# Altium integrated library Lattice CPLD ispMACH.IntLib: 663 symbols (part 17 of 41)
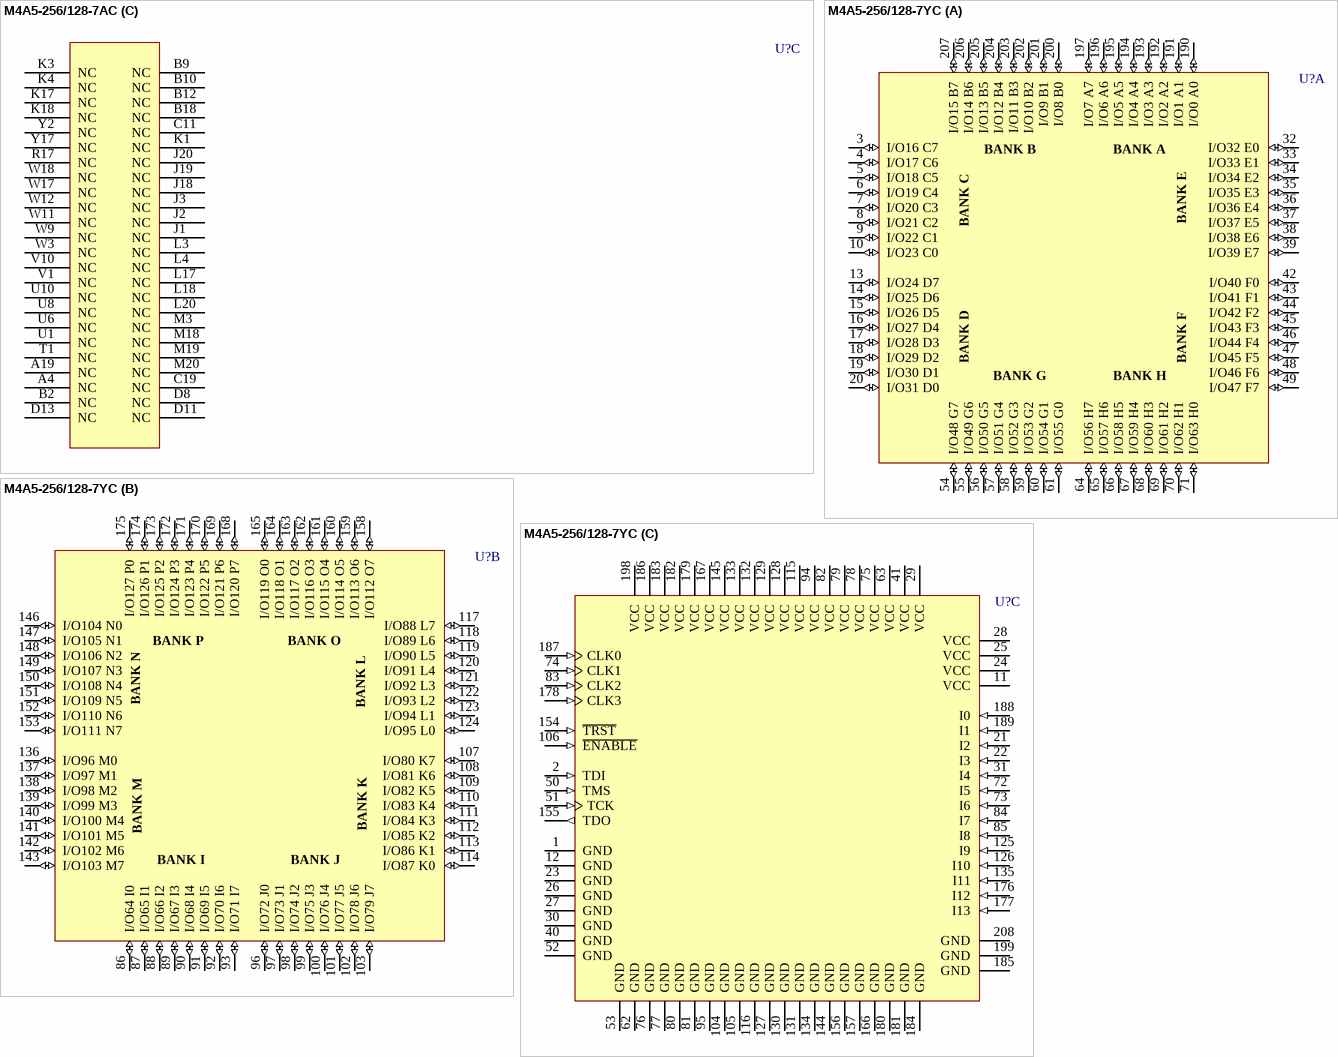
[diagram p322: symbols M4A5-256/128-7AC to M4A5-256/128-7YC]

## M4A5-256/128-7YC
designator U?
High-Performance EE CMOS In-System Programmable Logic
footprint PQFP208_N (Shrink QFP, 208-Leads, Body 28x28mm, Pitch 0.5mm, IPC Medium Density)
footprint PQFP208_L (Shrink QFP, 208-Leads, Body 28x28mm, Pitch 0.5mm, IPC High Density)
footprint PQFP208_M (Shrink QFP, 208-Leads, Body 28x28mm, Pitch 0.5mm, IPC Low Density)
3D model M4A5-PQFP208 (208-Pin Plastic Quad Flat Pack (PQFP208))
part A pins: 3 I/O16 C7 (io), 4 I/O17 C6 (io), 5 I/O18 C5 (io), 6 I/O19 C4 (io), 7 I/O20 C3 (io), 8 I/O21 C2 (io), 9 I/O22 C1 (io), 10 I/O23 C0 (io), 13 I/O24 D7 (io), 14 I/O25 D6 (io), 15 I/O26 D5 (io), 16 I/O27 D4 (io), 17 I/O28 D3 (io), 18 I/O29 D2 (io), 19 I/O30 D1 (io), 20 I/O31 D0 (io), 32 I/O32 E0 (io), 33 I/O33 E1 (io), 34 I/O34 E2 (io), 35 I/O35 E3 (io), 36 I/O36 E4 (io), 37 I/O37 E5 (io), 38 I/O38 E6 (io), 39 I/O39 E7 (io), 42 I/O40 F0 (io), 43 I/O41 F1 (io), 44 I/O42 F2 (io), 45 I/O43 F3 (io), 46 I/O44 F4 (io), 47 I/O45 F5 (io), 48 I/O46 F6 (io), 49 I/O47 F7 (io), 54 I/O48 G7 (io), 55 I/O49 G6 (io), 56 I/O50 G5 (io), 57 I/O51 G4 (io), 58 I/O52 G3 (io), 59 I/O53 G2 (io), 60 I/O54 G1 (io), 61 I/O55 G0 (io), 64 I/O56 H7 (io), 65 I/O57 H6 (io), 66 I/O58 H5 (io), 67 I/O59 H4 (io), 68 I/O60 H3 (io), 69 I/O61 H2 (io), 70 I/O62 H1 (io), 71 I/O63 H0 (io), 190 I/O0 A0 (io), 191 I/O1 A1 (io), 192 I/O2 A2 (io), 193 I/O3 A3 (io), 194 I/O4 A4 (io), 195 I/O5 A5 (io), 196 I/O6 A6 (io), 197 I/O7 A7 (io), 200 I/O8 B0 (io), 201 I/O9 B1 (io), 202 I/O10 B2 (io), 203 I/O11 B3 (io), 204 I/O12 B4 (io), 205 I/O13 B5 (io), 206 I/O14 B6 (io), 207 I/O15 B7 (io)
part B pins: 86 I/O64 I0 (io), 87 I/O65 I1 (io), 88 I/O66 I2 (io), 89 I/O67 I3 (io), 90 I/O68 I4 (io), 91 I/O69 I5 (io), 92 I/O70 I6 (io), 93 I/O71 I7 (io), 96 I/O72 J0 (io), 97 I/O73 J1 (io), 98 I/O74 J2 (io), 99 I/O75 J3 (io), 100 I/O76 J4 (io), 101 I/O77 J5 (io), 102 I/O78 J6 (io), 103 I/O79 J7 (io), 107 I/O80 K7 (io), 108 I/O81 K6 (io), 109 I/O82 K5 (io), 110 I/O83 K4 (io), 111 I/O84 K3 (io), 112 I/O85 K2 (io), 113 I/O86 K1 (io), 114 I/O87 K0 (io), 117 I/O88 L7 (io), 118 I/O89 L6 (io), 119 I/O90 L5 (io), 120 I/O91 L4 (io), 121 I/O92 L3 (io), 122 I/O93 L2 (io), 123 I/O94 L1 (io), 124 I/O95 L0 (io), 136 I/O96 M0 (io), 137 I/O97 M1 (io), 138 I/O98 M2 (io), 139 I/O99 M3 (io), 140 I/O100 M4 (io), 141 I/O101 M5 (io), 142 I/O102 M6 (io), 143 I/O103 M7 (io), 146 I/O104 N0 (io), 147 I/O105 N1 (io), 148 I/O106 N2 (io), 149 I/O107 N3 (io), 150 I/O108 N4 (io), 151 I/O109 N5 (io), 152 I/O110 N6 (io), 153 I/O111 N7 (io), 158 I/O112 O7 (io), 159 I/O113 O6 (io), 160 I/O114 O5 (io), 161 I/O115 O4 (io), 162 I/O116 O3 (io), 163 I/O117 O2 (io), 164 I/O118 O1 (io), 165 I/O119 O0 (io), 168 I/O120 P7 (io), 169 I/O121 P6 (io), 170 I/O122 P5 (io), 171 I/O123 P4 (io), 172 I/O124 P3 (io), 173 I/O125 P2 (io), 174 I/O126 P1 (io), 175 I/O127 P0 (io)
part C pins: 1 GND (power), 2 TDI (in), 11 VCC (power), 12 GND (power), 21 I2 (in), 22 I3 (in), 23 GND (power), 24 VCC (power), 25 VCC (power), 26 GND (power), 27 GND (power), 28 VCC (power), 29 VCC (power), 30 GND (power), 31 I4 (in), 40 GND (power), 41 VCC (power), 50 TMS (in), 51 TCK (in), 52 GND (power), 53 GND (power), 62 GND (power), 63 VCC (power), 72 I5 (in), 73 I6 (in), 74 CLK1 (in), 75 VCC (power), 76 GND (power), 77 GND (power), 78 VCC (power), 79 VCC (power), 80 GND (power), 81 GND (power), 82 VCC (power), 83 CLK2 (in), 84 I7 (in), 85 I8 (in), 94 VCC (power), 95 GND (power), 104 GND (power), 105 GND (power), 106 ~{ENABLE} (in), 115 VCC (power), 116 GND (power), 125 I9 (in), 126 I10 (in), 127 GND (power), 128 VCC (power), 129 VCC (power), 130 GND (power), 131 GND (power), 132 VCC (power), 133 VCC (power), 134 GND (power), 135 I11 (in), 144 GND (power), 145 VCC (power), 154 ~{TRST} (in), 155 TDO (out), 156 GND (power), 157 GND (power), 166 GND (power), 167 VCC (power), 176 I12 (in), 177 I13 (in), 178 CLK3 (in), 179 VCC (power), 180 GND (power), 181 GND (power), 182 VCC (power), 183 VCC (power), 184 GND (power), 185 GND (power), 186 VCC (power), 187 CLK0 (in), 188 I0 (in), 189 I1 (in), 198 VCC (power), 199 GND (power), 208 GND (power)

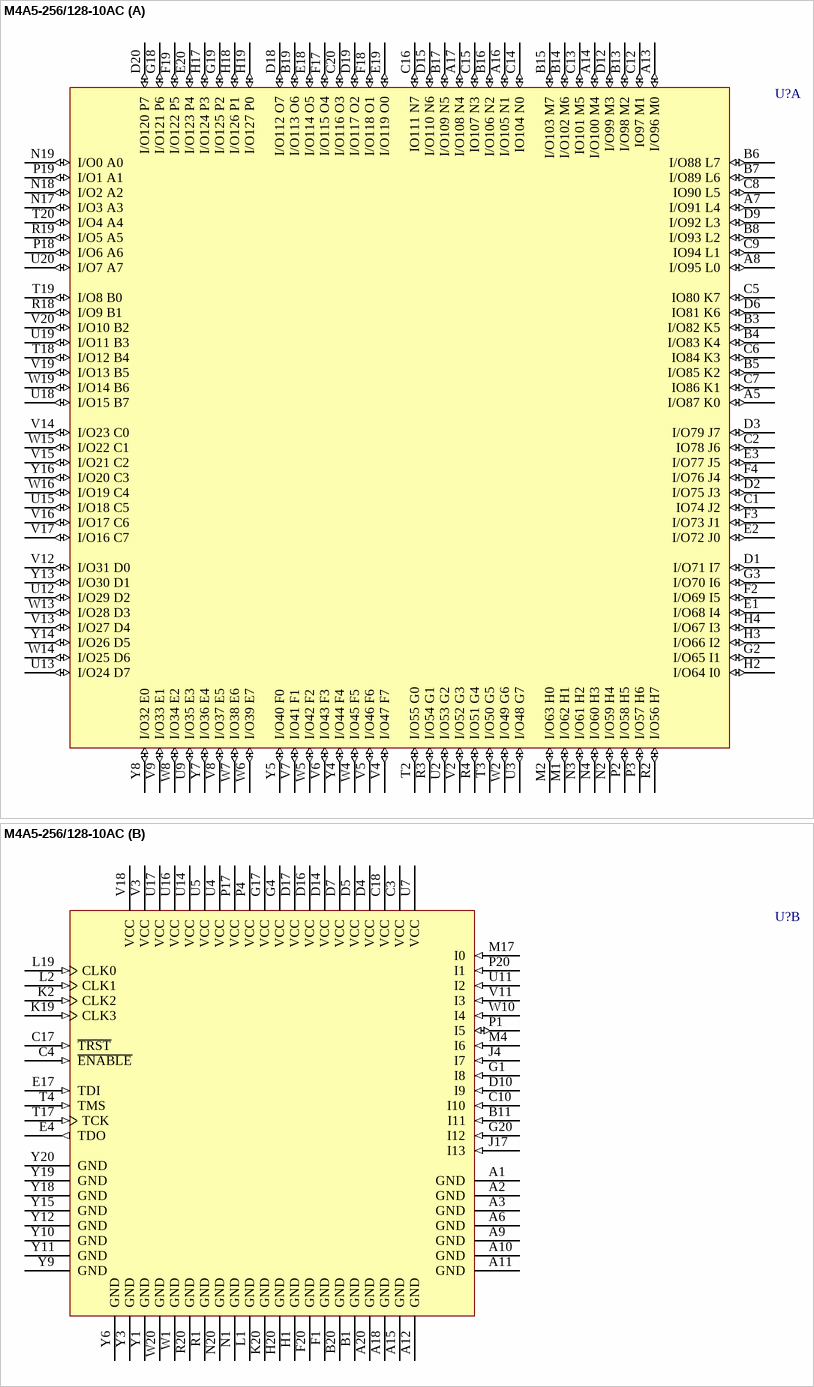
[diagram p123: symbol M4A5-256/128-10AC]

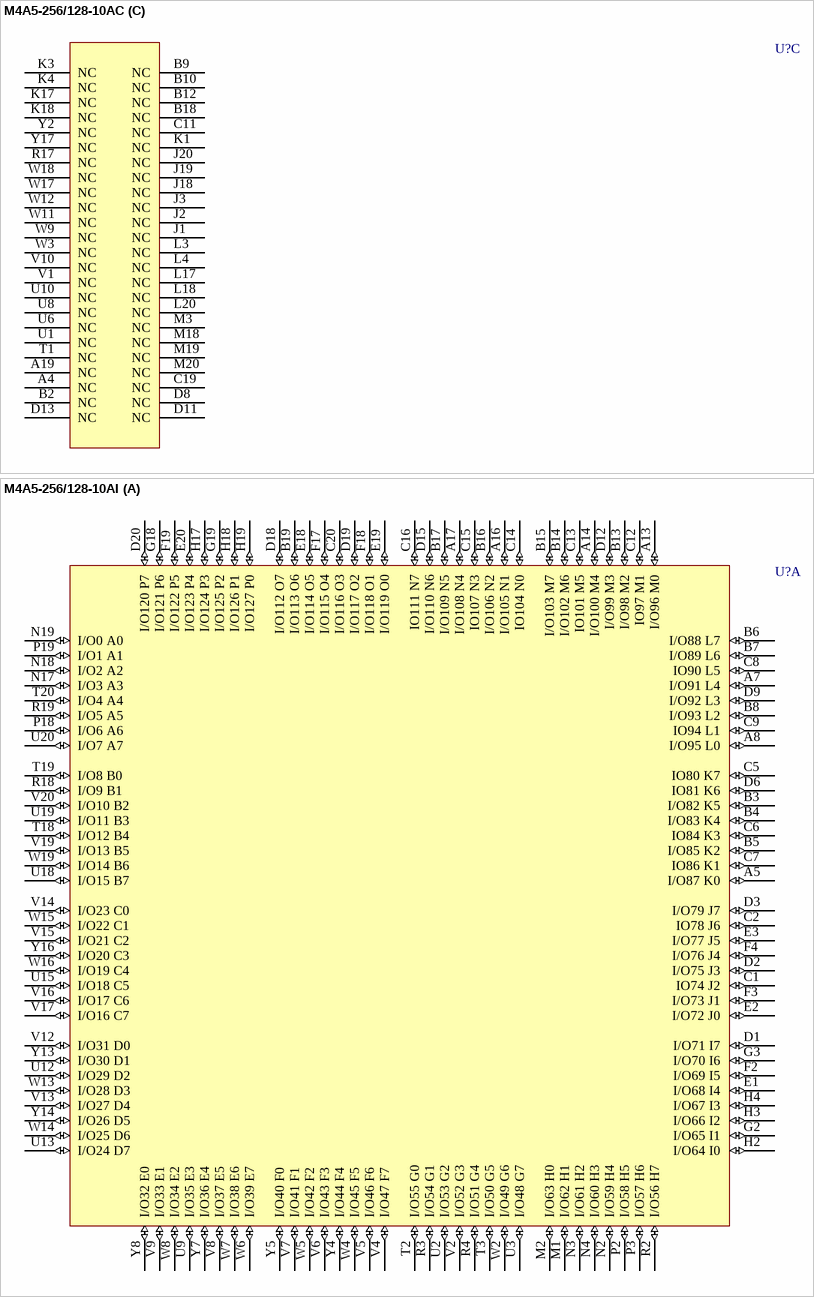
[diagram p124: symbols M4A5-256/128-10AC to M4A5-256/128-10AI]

## M4A5-256/128-10AC
designator U?
High-Performance EE CMOS In-System Programmable Logic
footprint SBGA256 (BGA, 256-Leads, Body 27x27mm, Pitch 1.27mm)
3D model M4A5-SBGA256 (256-Ball Super Ball Grid Array (SBGA256))
part A pins: A5 I/O87 K0 (io), A7 I/O91 L4 (io), A8 I/O95 L0 (io), A13 I/O96 M0 (io), A14 I/O100 M4 (io), A16 I/O105 N1 (io), A17 I/O108 N4 (io), B3 I/O82 K5 (io), B4 I/O83 K4 (io), B5 I/O85 K2 (io), B6 I/O88 L7 (io), B7 I/O89 L6 (io), B8 I/O93 L2 (io), B13 I/O98 M2 (io), B14 I/O102 M6 (io), B15 I/O103 M7 (io), B16 I/O106 N2 (io), B17 I/O109 N5 (io), B19 I/O113 O6 (io), C1 IO74 J2 (io), C2 IO78 J6 (io), C5 IO80 K7 (io), C6 IO84 K3 (io), C7 IO86 K1 (io), C8 IO90 L5 (io), C9 IO94 L1 (io), C12 IO97 M1 (io), C13 IO101 M5 (io), C14 IO104 N0 (io), C15 IO107 N3 (io), C16 IO111 N7 (io), C20 I/O116 O3 (io), D1 I/O71 I7 (io), D2 I/O75 J3 (io), D3 I/O79 J7 (io), D6 IO81 K6 (io), D9 I/O92 L3 (io), D12 I/O99 M3 (io), D15 I/O110 N6 (io), D18 I/O112 O7 (io), D19 I/O117 O2 (io), D20 I/O120 P7 (io), E1 I/O68 I4 (io), E2 I/O72 J0 (io), E3 I/O77 J5 (io), E18 I/O114 O5 (io), E19 I/O119 O0 (io), E20 I/O123 P4 (io), F2 I/O69 I5 (io), F3 I/O73 J1 (io), F4 I/O76 J4 (io), F17 I/O115 O4 (io), F18 I/O118 O1 (io), F19 I/O122 P5 (io), G2 I/O65 I1 (io), G3 I/O70 I6 (io), G18 I/O121 P6 (io), G19 I/O125 P2 (io), H2 I/O64 I0 (io), H3 I/O66 I2 (io), H4 I/O67 I3 (io), H17 I/O124 P3 (io), H18 I/O126 P1 (io), H19 I/O127 P0 (io), M1 I/O62 H1 (io), M2 I/O63 H0 (io), N2 I/O59 H4 (io), N3 I/O61 H2 (io), N4 I/O60 H3 (io), N17 I/O3 A3 (io), N18 I/O2 A2 (io), N19 I/O0 A0 (io), P2 I/O58 H5 (io), P3 I/O57 H6 (io), P18 I/O6 A6 (io), P19 I/O1 A1 (io), R2 I/O56 H7 (io), R3 I/O54 G1 (io), R4 I/O51 G4 (io), R18 I/O9 B1 (io), R19 I/O5 A5 (io), T2 I/O55 G0 (io), T3 I/O50 G5 (io), T18 I/O12 B4 (io), T19 I/O8 B0 (io), T20 I/O4 A4 (io), U2 I/O53 G2 (io), U3 I/O48 G7 (io), U9 I/O35 E3 (io), U12 I/O29 D2 (io), U13 I/O24 D7 (io), U15 I/O18 C5 (io), U18 I/O15 B7 (io), U19 I/O11 B3 (io), U20 I/O7 A7 (io), V2 I/O52 G3 (io), V4 I/O47 F7 (io), V5 I/O46 F6 (io), V6 I/O43 F3 (io), V7 I/O41 F1 (io), V8 I/O37 E5 (io), V9 I/O33 E1 (io), V12 I/O31 D0 (io), V13 I/O27 D4 (io), V14 I/O23 C0 (io), V15 I/O21 C2 (io), V16 I/O17 C6 (io), V17 I/O16 C7 (io), V19 I/O13 B5 (io), V20 I/O10 B2 (io), W2 I/O49 G6 (io), W4 I/O45 F5 (io), W5 I/O42 F2 (io), W6 I/O39 E7 (io), W7 I/O38 E6 (io), W8 I/O34 E2 (io), W13 I/O28 D3 (io), W14 I/O25 D6 (io), W15 I/O22 C1 (io), W16 I/O19 C4 (io), W19 I/O14 B6 (io), Y4 I/O44 F4 (io), Y5 I/O40 F0 (io), Y7 I/O36 E4 (io), Y8 I/O32 E0 (io), Y13 I/O30 D1 (io), Y14 I/O26 D5 (io), Y16 I/O20 C3 (io)
part B pins: A1 GND (power), A2 GND (power), A3 GND (power), A6 GND (power), A9 GND (power), A10 GND (power), A11 GND (power), A12 GND (power), A15 GND (power), A18 GND (power), A20 GND (power), B1 GND (power), B11 I11 (in), B20 GND (power), C3 VCC (power), C4 ~{ENABLE} (in), C10 I10 (in), C17 ~{TRST} (in), C18 VCC (power), D4 VCC (power), D5 VCC (power), D7 VCC (power), D10 I9 (in), D14 VCC (power), D16 VCC (power), D17 VCC (power), E4 TDO (out), E17 TDI (in), F1 GND (power), F20 GND (power), G1 I8 (in), G4 VCC (power), G17 VCC (power), G20 I12 (in), H1 GND (power), H20 GND (power), J4 I7 (in), J17 I13 (in), K2 CLK2 (in), K19 CLK3 (in), K20 GND (power), L1 GND (power), L2 CLK1 (in), L19 CLK0 (in), M4 I6 (in), M17 I0 (in), N1 GND (power), N20 GND (power), P1 I5 (io), P4 VCC (power), P17 VCC (power), P20 I1 (in), R1 GND (power), R20 GND (power), T4 TMS (in), T17 TCK (in), U4 VCC (power), U5 VCC (power), U7 VCC (power), U11 I2 (in), U14 VCC (power), U16 VCC (power), U17 VCC (power), V3 VCC (power), V11 I3 (in), V18 VCC (power), W1 GND (power), W10 I4 (in), W20 GND (power), Y1 GND (power), Y3 GND (power), Y6 GND (power), Y9 GND (power), Y10 GND (power), Y11 GND (power), Y12 GND (power), Y15 GND (power), Y18 GND (power), Y19 GND (power), Y20 GND (power)
part C pins: A4 NC, A19 NC, B2 NC, B9 NC, B10 NC, B12 NC, B18 NC, C11 NC, C19 NC, D8 NC, D11 NC, D13 NC, J1 NC, J2 NC, J3 NC, J18 NC, J19 NC, J20 NC, K1 NC, K3 NC, K4 NC, K17 NC, K18 NC, L3 NC, L4 NC, L17 NC, L18 NC, L20 NC, M3 NC, M18 NC, M19 NC, M20 NC, R17 NC, T1 NC, U1 NC, U6 NC, U8 NC, U10 NC, V1 NC, V10 NC, W3 NC, W9 NC, W11 NC, W12 NC, W17 NC, W18 NC, Y2 NC, Y17 NC

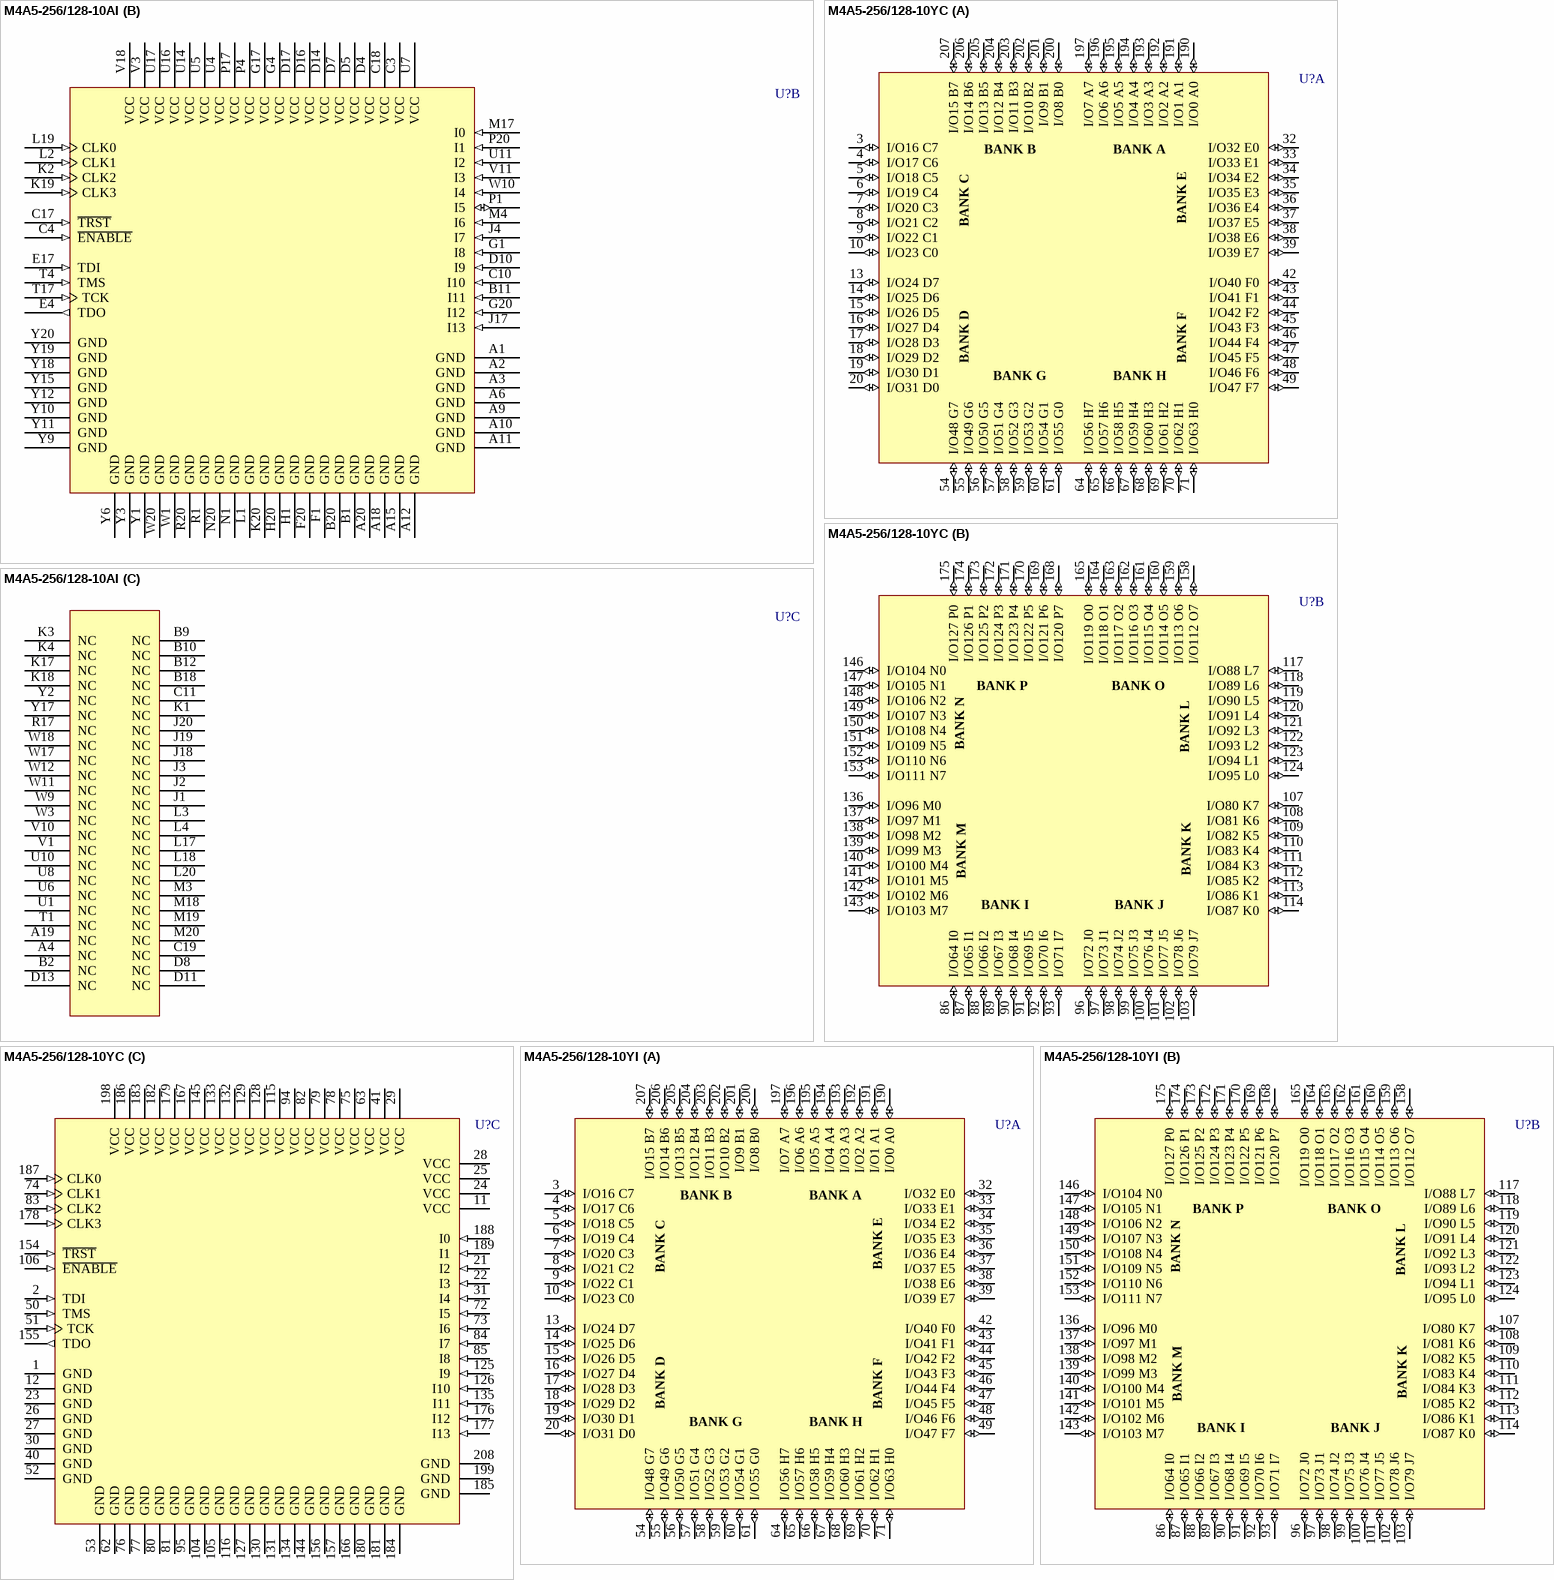
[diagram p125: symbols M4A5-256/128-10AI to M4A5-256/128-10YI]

## M4A5-256/128-10AI
designator U?
High-Performance EE CMOS In-System Programmable Logic
footprint SBGA256 (BGA, 256-Leads, Body 27x27mm, Pitch 1.27mm)
3D model M4A5-SBGA256 (256-Ball Super Ball Grid Array (SBGA256))
part A pins: A5 I/O87 K0 (io), A7 I/O91 L4 (io), A8 I/O95 L0 (io), A13 I/O96 M0 (io), A14 I/O100 M4 (io), A16 I/O105 N1 (io), A17 I/O108 N4 (io), B3 I/O82 K5 (io), B4 I/O83 K4 (io), B5 I/O85 K2 (io), B6 I/O88 L7 (io), B7 I/O89 L6 (io), B8 I/O93 L2 (io), B13 I/O98 M2 (io), B14 I/O102 M6 (io), B15 I/O103 M7 (io), B16 I/O106 N2 (io), B17 I/O109 N5 (io), B19 I/O113 O6 (io), C1 IO74 J2 (io), C2 IO78 J6 (io), C5 IO80 K7 (io), C6 IO84 K3 (io), C7 IO86 K1 (io), C8 IO90 L5 (io), C9 IO94 L1 (io), C12 IO97 M1 (io), C13 IO101 M5 (io), C14 IO104 N0 (io), C15 IO107 N3 (io), C16 IO111 N7 (io), C20 I/O116 O3 (io), D1 I/O71 I7 (io), D2 I/O75 J3 (io), D3 I/O79 J7 (io), D6 IO81 K6 (io), D9 I/O92 L3 (io), D12 I/O99 M3 (io), D15 I/O110 N6 (io), D18 I/O112 O7 (io), D19 I/O117 O2 (io), D20 I/O120 P7 (io), E1 I/O68 I4 (io), E2 I/O72 J0 (io), E3 I/O77 J5 (io), E18 I/O114 O5 (io), E19 I/O119 O0 (io), E20 I/O123 P4 (io), F2 I/O69 I5 (io), F3 I/O73 J1 (io), F4 I/O76 J4 (io), F17 I/O115 O4 (io), F18 I/O118 O1 (io), F19 I/O122 P5 (io), G2 I/O65 I1 (io), G3 I/O70 I6 (io), G18 I/O121 P6 (io), G19 I/O125 P2 (io), H2 I/O64 I0 (io), H3 I/O66 I2 (io), H4 I/O67 I3 (io), H17 I/O124 P3 (io), H18 I/O126 P1 (io), H19 I/O127 P0 (io), M1 I/O62 H1 (io), M2 I/O63 H0 (io), N2 I/O59 H4 (io), N3 I/O61 H2 (io), N4 I/O60 H3 (io), N17 I/O3 A3 (io), N18 I/O2 A2 (io), N19 I/O0 A0 (io), P2 I/O58 H5 (io), P3 I/O57 H6 (io), P18 I/O6 A6 (io), P19 I/O1 A1 (io), R2 I/O56 H7 (io), R3 I/O54 G1 (io), R4 I/O51 G4 (io), R18 I/O9 B1 (io), R19 I/O5 A5 (io), T2 I/O55 G0 (io), T3 I/O50 G5 (io), T18 I/O12 B4 (io), T19 I/O8 B0 (io), T20 I/O4 A4 (io), U2 I/O53 G2 (io), U3 I/O48 G7 (io), U9 I/O35 E3 (io), U12 I/O29 D2 (io), U13 I/O24 D7 (io), U15 I/O18 C5 (io), U18 I/O15 B7 (io), U19 I/O11 B3 (io), U20 I/O7 A7 (io), V2 I/O52 G3 (io), V4 I/O47 F7 (io), V5 I/O46 F6 (io), V6 I/O43 F3 (io), V7 I/O41 F1 (io), V8 I/O37 E5 (io), V9 I/O33 E1 (io), V12 I/O31 D0 (io), V13 I/O27 D4 (io), V14 I/O23 C0 (io), V15 I/O21 C2 (io), V16 I/O17 C6 (io), V17 I/O16 C7 (io), V19 I/O13 B5 (io), V20 I/O10 B2 (io), W2 I/O49 G6 (io), W4 I/O45 F5 (io), W5 I/O42 F2 (io), W6 I/O39 E7 (io), W7 I/O38 E6 (io), W8 I/O34 E2 (io), W13 I/O28 D3 (io), W14 I/O25 D6 (io), W15 I/O22 C1 (io), W16 I/O19 C4 (io), W19 I/O14 B6 (io), Y4 I/O44 F4 (io), Y5 I/O40 F0 (io), Y7 I/O36 E4 (io), Y8 I/O32 E0 (io), Y13 I/O30 D1 (io), Y14 I/O26 D5 (io), Y16 I/O20 C3 (io)
part B pins: A1 GND (power), A2 GND (power), A3 GND (power), A6 GND (power), A9 GND (power), A10 GND (power), A11 GND (power), A12 GND (power), A15 GND (power), A18 GND (power), A20 GND (power), B1 GND (power), B11 I11 (in), B20 GND (power), C3 VCC (power), C4 ~{ENABLE} (in), C10 I10 (in), C17 ~{TRST} (in), C18 VCC (power), D4 VCC (power), D5 VCC (power), D7 VCC (power), D10 I9 (in), D14 VCC (power), D16 VCC (power), D17 VCC (power), E4 TDO (out), E17 TDI (in), F1 GND (power), F20 GND (power), G1 I8 (in), G4 VCC (power), G17 VCC (power), G20 I12 (in), H1 GND (power), H20 GND (power), J4 I7 (in), J17 I13 (in), K2 CLK2 (in), K19 CLK3 (in), K20 GND (power), L1 GND (power), L2 CLK1 (in), L19 CLK0 (in), M4 I6 (in), M17 I0 (in), N1 GND (power), N20 GND (power), P1 I5 (io), P4 VCC (power), P17 VCC (power), P20 I1 (in), R1 GND (power), R20 GND (power), T4 TMS (in), T17 TCK (in), U4 VCC (power), U5 VCC (power), U7 VCC (power), U11 I2 (in), U14 VCC (power), U16 VCC (power), U17 VCC (power), V3 VCC (power), V11 I3 (in), V18 VCC (power), W1 GND (power), W10 I4 (in), W20 GND (power), Y1 GND (power), Y3 GND (power), Y6 GND (power), Y9 GND (power), Y10 GND (power), Y11 GND (power), Y12 GND (power), Y15 GND (power), Y18 GND (power), Y19 GND (power), Y20 GND (power)
part C pins: A4 NC, A19 NC, B2 NC, B9 NC, B10 NC, B12 NC, B18 NC, C11 NC, C19 NC, D8 NC, D11 NC, D13 NC, J1 NC, J2 NC, J3 NC, J18 NC, J19 NC, J20 NC, K1 NC, K3 NC, K4 NC, K17 NC, K18 NC, L3 NC, L4 NC, L17 NC, L18 NC, L20 NC, M3 NC, M18 NC, M19 NC, M20 NC, R17 NC, T1 NC, U1 NC, U6 NC, U8 NC, U10 NC, V1 NC, V10 NC, W3 NC, W9 NC, W11 NC, W12 NC, W17 NC, W18 NC, Y2 NC, Y17 NC

## M4A5-256/128-10YC
designator U?
High-Performance EE CMOS In-System Programmable Logic
footprint PQFP208_N (Shrink QFP, 208-Leads, Body 28x28mm, Pitch 0.5mm, IPC Medium Density)
footprint PQFP208_L (Shrink QFP, 208-Leads, Body 28x28mm, Pitch 0.5mm, IPC High Density)
footprint PQFP208_M (Shrink QFP, 208-Leads, Body 28x28mm, Pitch 0.5mm, IPC Low Density)
3D model M4A5-PQFP208 (208-Pin Plastic Quad Flat Pack (PQFP208))
part A pins: 3 I/O16 C7 (io), 4 I/O17 C6 (io), 5 I/O18 C5 (io), 6 I/O19 C4 (io), 7 I/O20 C3 (io), 8 I/O21 C2 (io), 9 I/O22 C1 (io), 10 I/O23 C0 (io), 13 I/O24 D7 (io), 14 I/O25 D6 (io), 15 I/O26 D5 (io), 16 I/O27 D4 (io), 17 I/O28 D3 (io), 18 I/O29 D2 (io), 19 I/O30 D1 (io), 20 I/O31 D0 (io), 32 I/O32 E0 (io), 33 I/O33 E1 (io), 34 I/O34 E2 (io), 35 I/O35 E3 (io), 36 I/O36 E4 (io), 37 I/O37 E5 (io), 38 I/O38 E6 (io), 39 I/O39 E7 (io), 42 I/O40 F0 (io), 43 I/O41 F1 (io), 44 I/O42 F2 (io), 45 I/O43 F3 (io), 46 I/O44 F4 (io), 47 I/O45 F5 (io), 48 I/O46 F6 (io), 49 I/O47 F7 (io), 54 I/O48 G7 (io), 55 I/O49 G6 (io), 56 I/O50 G5 (io), 57 I/O51 G4 (io), 58 I/O52 G3 (io), 59 I/O53 G2 (io), 60 I/O54 G1 (io), 61 I/O55 G0 (io), 64 I/O56 H7 (io), 65 I/O57 H6 (io), 66 I/O58 H5 (io), 67 I/O59 H4 (io), 68 I/O60 H3 (io), 69 I/O61 H2 (io), 70 I/O62 H1 (io), 71 I/O63 H0 (io), 190 I/O0 A0 (io), 191 I/O1 A1 (io), 192 I/O2 A2 (io), 193 I/O3 A3 (io), 194 I/O4 A4 (io), 195 I/O5 A5 (io), 196 I/O6 A6 (io), 197 I/O7 A7 (io), 200 I/O8 B0 (io), 201 I/O9 B1 (io), 202 I/O10 B2 (io), 203 I/O11 B3 (io), 204 I/O12 B4 (io), 205 I/O13 B5 (io), 206 I/O14 B6 (io), 207 I/O15 B7 (io)
part B pins: 86 I/O64 I0 (io), 87 I/O65 I1 (io), 88 I/O66 I2 (io), 89 I/O67 I3 (io), 90 I/O68 I4 (io), 91 I/O69 I5 (io), 92 I/O70 I6 (io), 93 I/O71 I7 (io), 96 I/O72 J0 (io), 97 I/O73 J1 (io), 98 I/O74 J2 (io), 99 I/O75 J3 (io), 100 I/O76 J4 (io), 101 I/O77 J5 (io), 102 I/O78 J6 (io), 103 I/O79 J7 (io), 107 I/O80 K7 (io), 108 I/O81 K6 (io), 109 I/O82 K5 (io), 110 I/O83 K4 (io), 111 I/O84 K3 (io), 112 I/O85 K2 (io), 113 I/O86 K1 (io), 114 I/O87 K0 (io), 117 I/O88 L7 (io), 118 I/O89 L6 (io), 119 I/O90 L5 (io), 120 I/O91 L4 (io), 121 I/O92 L3 (io), 122 I/O93 L2 (io), 123 I/O94 L1 (io), 124 I/O95 L0 (io), 136 I/O96 M0 (io), 137 I/O97 M1 (io), 138 I/O98 M2 (io), 139 I/O99 M3 (io), 140 I/O100 M4 (io), 141 I/O101 M5 (io), 142 I/O102 M6 (io), 143 I/O103 M7 (io), 146 I/O104 N0 (io), 147 I/O105 N1 (io), 148 I/O106 N2 (io), 149 I/O107 N3 (io), 150 I/O108 N4 (io), 151 I/O109 N5 (io), 152 I/O110 N6 (io), 153 I/O111 N7 (io), 158 I/O112 O7 (io), 159 I/O113 O6 (io), 160 I/O114 O5 (io), 161 I/O115 O4 (io), 162 I/O116 O3 (io), 163 I/O117 O2 (io), 164 I/O118 O1 (io), 165 I/O119 O0 (io), 168 I/O120 P7 (io), 169 I/O121 P6 (io), 170 I/O122 P5 (io), 171 I/O123 P4 (io), 172 I/O124 P3 (io), 173 I/O125 P2 (io), 174 I/O126 P1 (io), 175 I/O127 P0 (io)
part C pins: 1 GND (power), 2 TDI (in), 11 VCC (power), 12 GND (power), 21 I2 (in), 22 I3 (in), 23 GND (power), 24 VCC (power), 25 VCC (power), 26 GND (power), 27 GND (power), 28 VCC (power), 29 VCC (power), 30 GND (power), 31 I4 (in), 40 GND (power), 41 VCC (power), 50 TMS (in), 51 TCK (in), 52 GND (power), 53 GND (power), 62 GND (power), 63 VCC (power), 72 I5 (in), 73 I6 (in), 74 CLK1 (in), 75 VCC (power), 76 GND (power), 77 GND (power), 78 VCC (power), 79 VCC (power), 80 GND (power), 81 GND (power), 82 VCC (power), 83 CLK2 (in), 84 I7 (in), 85 I8 (in), 94 VCC (power), 95 GND (power), 104 GND (power), 105 GND (power), 106 ~{ENABLE} (in), 115 VCC (power), 116 GND (power), 125 I9 (in), 126 I10 (in), 127 GND (power), 128 VCC (power), 129 VCC (power), 130 GND (power), 131 GND (power), 132 VCC (power), 133 VCC (power), 134 GND (power), 135 I11 (in), 144 GND (power), 145 VCC (power), 154 ~{TRST} (in), 155 TDO (out), 156 GND (power), 157 GND (power), 166 GND (power), 167 VCC (power), 176 I12 (in), 177 I13 (in), 178 CLK3 (in), 179 VCC (power), 180 GND (power), 181 GND (power), 182 VCC (power), 183 VCC (power), 184 GND (power), 185 GND (power), 186 VCC (power), 187 CLK0 (in), 188 I0 (in), 189 I1 (in), 198 VCC (power), 199 GND (power), 208 GND (power)

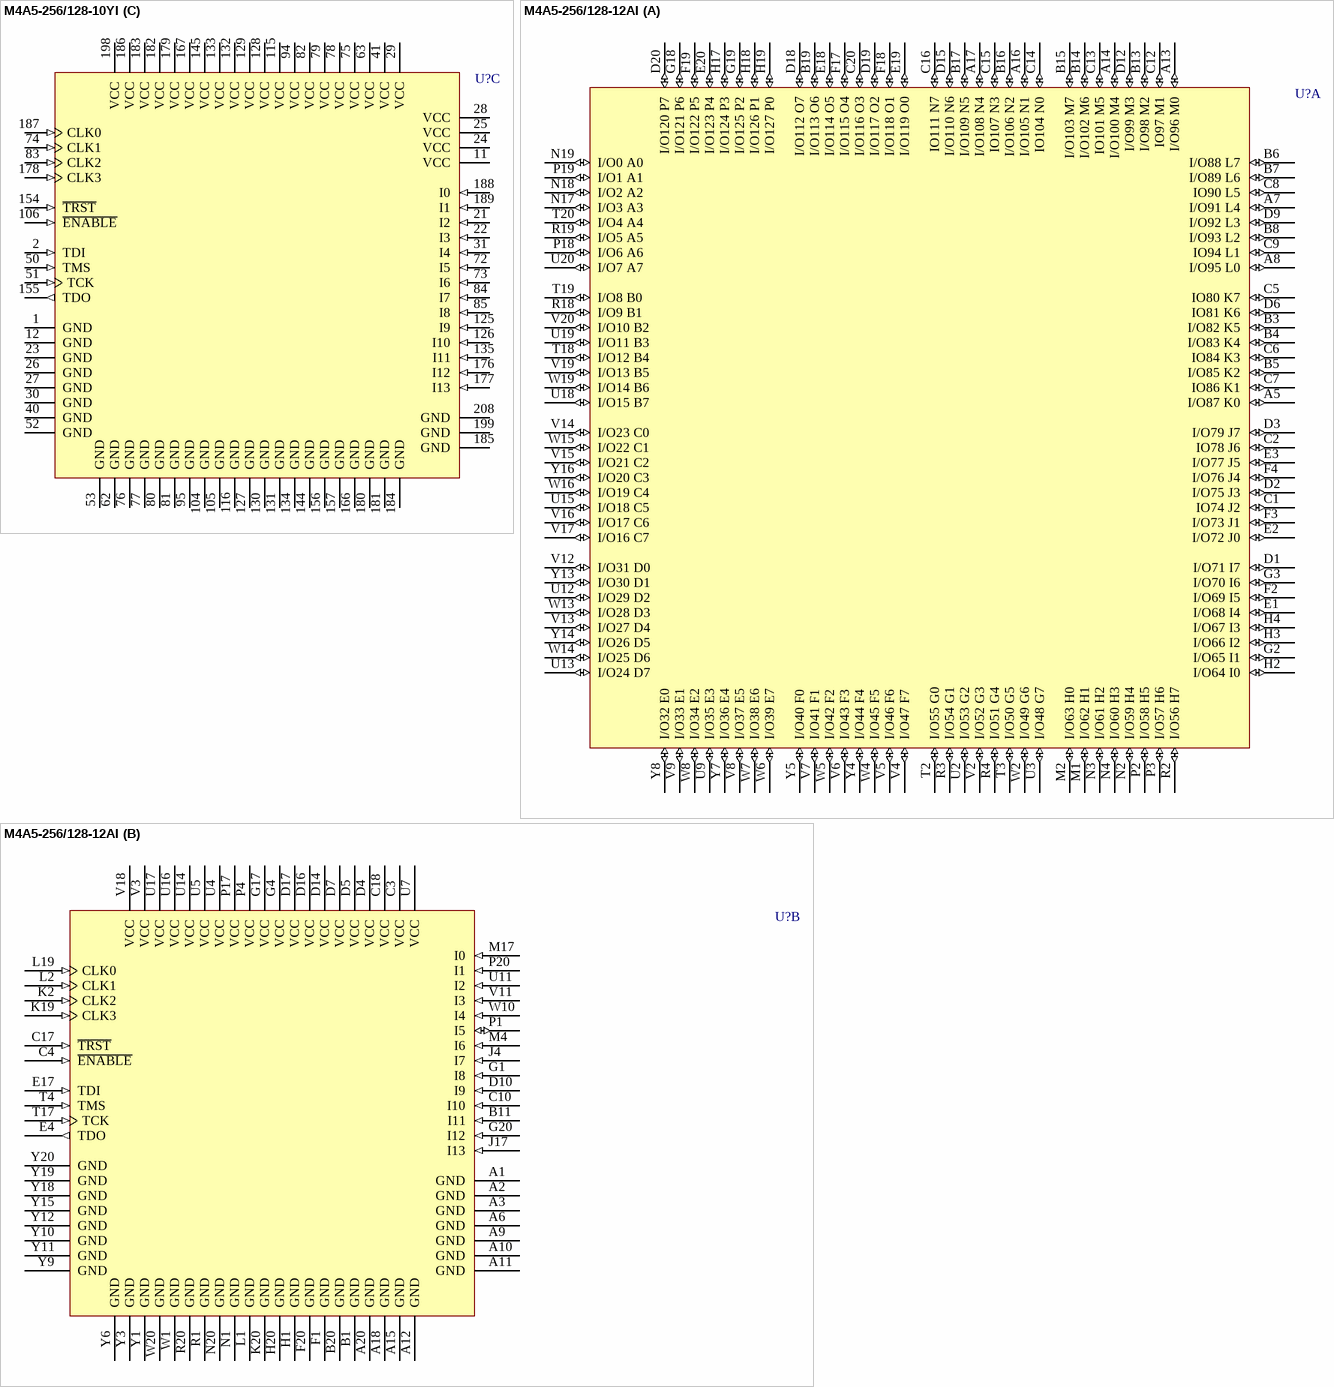
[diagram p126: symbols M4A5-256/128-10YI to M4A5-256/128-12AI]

## M4A5-256/128-10YI
designator U?
High-Performance EE CMOS In-System Programmable Logic
footprint PQFP208_N (Shrink QFP, 208-Leads, Body 28x28mm, Pitch 0.5mm, IPC Medium Density)
footprint PQFP208_L (Shrink QFP, 208-Leads, Body 28x28mm, Pitch 0.5mm, IPC High Density)
footprint PQFP208_M (Shrink QFP, 208-Leads, Body 28x28mm, Pitch 0.5mm, IPC Low Density)
3D model M4A5-PQFP208 (208-Pin Plastic Quad Flat Pack (PQFP208))
part A pins: 3 I/O16 C7 (io), 4 I/O17 C6 (io), 5 I/O18 C5 (io), 6 I/O19 C4 (io), 7 I/O20 C3 (io), 8 I/O21 C2 (io), 9 I/O22 C1 (io), 10 I/O23 C0 (io), 13 I/O24 D7 (io), 14 I/O25 D6 (io), 15 I/O26 D5 (io), 16 I/O27 D4 (io), 17 I/O28 D3 (io), 18 I/O29 D2 (io), 19 I/O30 D1 (io), 20 I/O31 D0 (io), 32 I/O32 E0 (io), 33 I/O33 E1 (io), 34 I/O34 E2 (io), 35 I/O35 E3 (io), 36 I/O36 E4 (io), 37 I/O37 E5 (io), 38 I/O38 E6 (io), 39 I/O39 E7 (io), 42 I/O40 F0 (io), 43 I/O41 F1 (io), 44 I/O42 F2 (io), 45 I/O43 F3 (io), 46 I/O44 F4 (io), 47 I/O45 F5 (io), 48 I/O46 F6 (io), 49 I/O47 F7 (io), 54 I/O48 G7 (io), 55 I/O49 G6 (io), 56 I/O50 G5 (io), 57 I/O51 G4 (io), 58 I/O52 G3 (io), 59 I/O53 G2 (io), 60 I/O54 G1 (io), 61 I/O55 G0 (io), 64 I/O56 H7 (io), 65 I/O57 H6 (io), 66 I/O58 H5 (io), 67 I/O59 H4 (io), 68 I/O60 H3 (io), 69 I/O61 H2 (io), 70 I/O62 H1 (io), 71 I/O63 H0 (io), 190 I/O0 A0 (io), 191 I/O1 A1 (io), 192 I/O2 A2 (io), 193 I/O3 A3 (io), 194 I/O4 A4 (io), 195 I/O5 A5 (io), 196 I/O6 A6 (io), 197 I/O7 A7 (io), 200 I/O8 B0 (io), 201 I/O9 B1 (io), 202 I/O10 B2 (io), 203 I/O11 B3 (io), 204 I/O12 B4 (io), 205 I/O13 B5 (io), 206 I/O14 B6 (io), 207 I/O15 B7 (io)
part B pins: 86 I/O64 I0 (io), 87 I/O65 I1 (io), 88 I/O66 I2 (io), 89 I/O67 I3 (io), 90 I/O68 I4 (io), 91 I/O69 I5 (io), 92 I/O70 I6 (io), 93 I/O71 I7 (io), 96 I/O72 J0 (io), 97 I/O73 J1 (io), 98 I/O74 J2 (io), 99 I/O75 J3 (io), 100 I/O76 J4 (io), 101 I/O77 J5 (io), 102 I/O78 J6 (io), 103 I/O79 J7 (io), 107 I/O80 K7 (io), 108 I/O81 K6 (io), 109 I/O82 K5 (io), 110 I/O83 K4 (io), 111 I/O84 K3 (io), 112 I/O85 K2 (io), 113 I/O86 K1 (io), 114 I/O87 K0 (io), 117 I/O88 L7 (io), 118 I/O89 L6 (io), 119 I/O90 L5 (io), 120 I/O91 L4 (io), 121 I/O92 L3 (io), 122 I/O93 L2 (io), 123 I/O94 L1 (io), 124 I/O95 L0 (io), 136 I/O96 M0 (io), 137 I/O97 M1 (io), 138 I/O98 M2 (io), 139 I/O99 M3 (io), 140 I/O100 M4 (io), 141 I/O101 M5 (io), 142 I/O102 M6 (io), 143 I/O103 M7 (io), 146 I/O104 N0 (io), 147 I/O105 N1 (io), 148 I/O106 N2 (io), 149 I/O107 N3 (io), 150 I/O108 N4 (io), 151 I/O109 N5 (io), 152 I/O110 N6 (io), 153 I/O111 N7 (io), 158 I/O112 O7 (io), 159 I/O113 O6 (io), 160 I/O114 O5 (io), 161 I/O115 O4 (io), 162 I/O116 O3 (io), 163 I/O117 O2 (io), 164 I/O118 O1 (io), 165 I/O119 O0 (io), 168 I/O120 P7 (io), 169 I/O121 P6 (io), 170 I/O122 P5 (io), 171 I/O123 P4 (io), 172 I/O124 P3 (io), 173 I/O125 P2 (io), 174 I/O126 P1 (io), 175 I/O127 P0 (io)
part C pins: 1 GND (power), 2 TDI (in), 11 VCC (power), 12 GND (power), 21 I2 (in), 22 I3 (in), 23 GND (power), 24 VCC (power), 25 VCC (power), 26 GND (power), 27 GND (power), 28 VCC (power), 29 VCC (power), 30 GND (power), 31 I4 (in), 40 GND (power), 41 VCC (power), 50 TMS (in), 51 TCK (in), 52 GND (power), 53 GND (power), 62 GND (power), 63 VCC (power), 72 I5 (in), 73 I6 (in), 74 CLK1 (in), 75 VCC (power), 76 GND (power), 77 GND (power), 78 VCC (power), 79 VCC (power), 80 GND (power), 81 GND (power), 82 VCC (power), 83 CLK2 (in), 84 I7 (in), 85 I8 (in), 94 VCC (power), 95 GND (power), 104 GND (power), 105 GND (power), 106 ~{ENABLE} (in), 115 VCC (power), 116 GND (power), 125 I9 (in), 126 I10 (in), 127 GND (power), 128 VCC (power), 129 VCC (power), 130 GND (power), 131 GND (power), 132 VCC (power), 133 VCC (power), 134 GND (power), 135 I11 (in), 144 GND (power), 145 VCC (power), 154 ~{TRST} (in), 155 TDO (out), 156 GND (power), 157 GND (power), 166 GND (power), 167 VCC (power), 176 I12 (in), 177 I13 (in), 178 CLK3 (in), 179 VCC (power), 180 GND (power), 181 GND (power), 182 VCC (power), 183 VCC (power), 184 GND (power), 185 GND (power), 186 VCC (power), 187 CLK0 (in), 188 I0 (in), 189 I1 (in), 198 VCC (power), 199 GND (power), 208 GND (power)

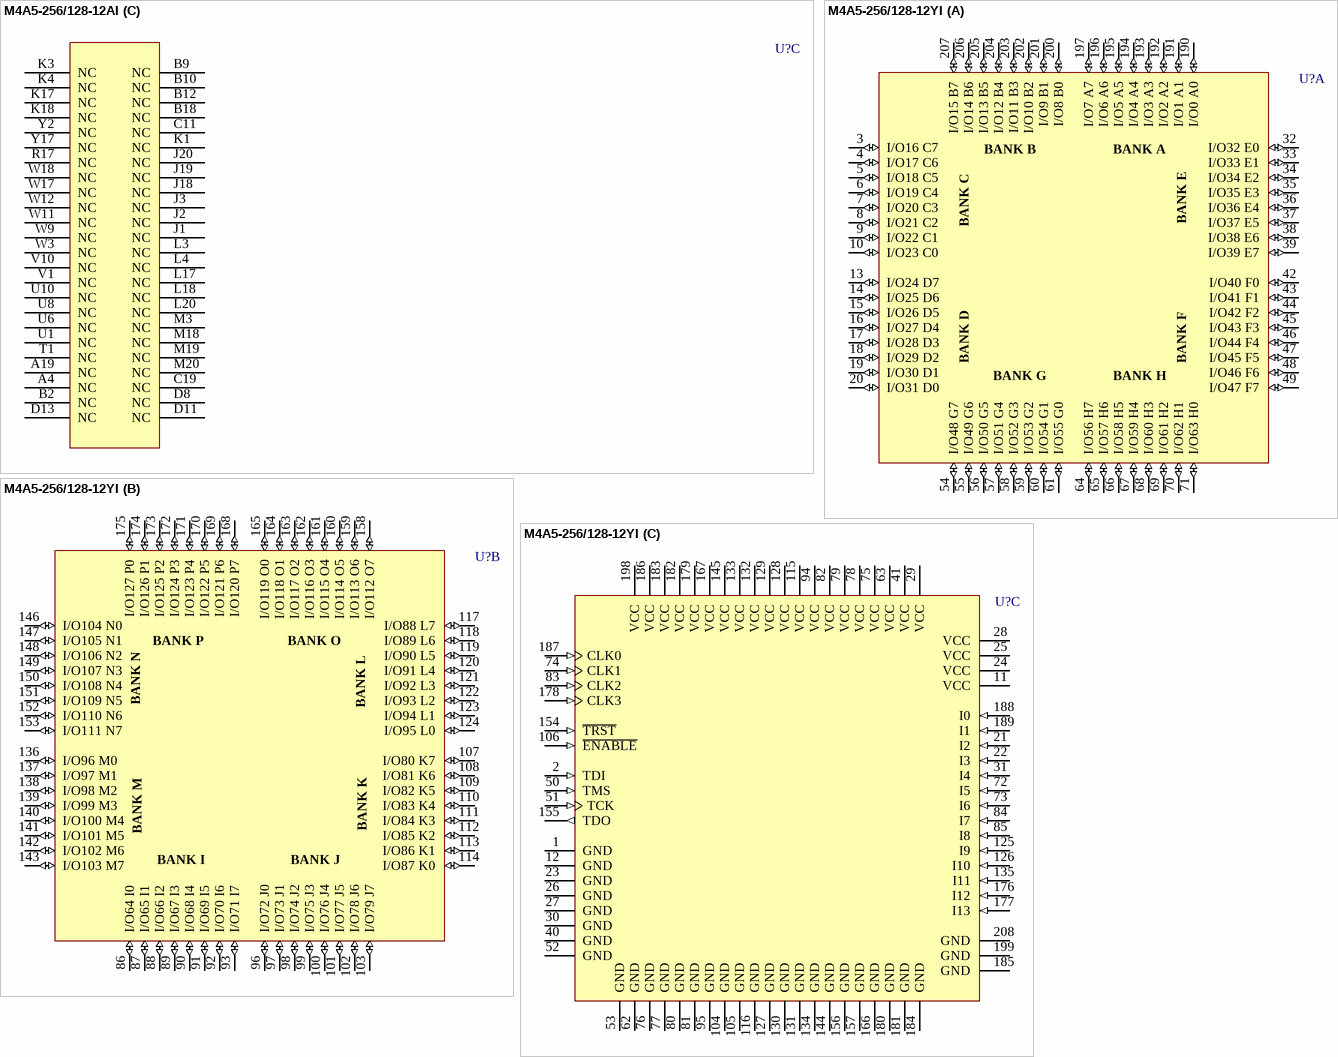
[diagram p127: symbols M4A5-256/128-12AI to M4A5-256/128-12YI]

## M4A5-256/128-12AI
designator U?
High-Performance EE CMOS In-System Programmable Logic
footprint SBGA256 (BGA, 256-Leads, Body 27x27mm, Pitch 1.27mm)
3D model M4A5-SBGA256 (256-Ball Super Ball Grid Array (SBGA256))
part A pins: A5 I/O87 K0 (io), A7 I/O91 L4 (io), A8 I/O95 L0 (io), A13 I/O96 M0 (io), A14 I/O100 M4 (io), A16 I/O105 N1 (io), A17 I/O108 N4 (io), B3 I/O82 K5 (io), B4 I/O83 K4 (io), B5 I/O85 K2 (io), B6 I/O88 L7 (io), B7 I/O89 L6 (io), B8 I/O93 L2 (io), B13 I/O98 M2 (io), B14 I/O102 M6 (io), B15 I/O103 M7 (io), B16 I/O106 N2 (io), B17 I/O109 N5 (io), B19 I/O113 O6 (io), C1 IO74 J2 (io), C2 IO78 J6 (io), C5 IO80 K7 (io), C6 IO84 K3 (io), C7 IO86 K1 (io), C8 IO90 L5 (io), C9 IO94 L1 (io), C12 IO97 M1 (io), C13 IO101 M5 (io), C14 IO104 N0 (io), C15 IO107 N3 (io), C16 IO111 N7 (io), C20 I/O116 O3 (io), D1 I/O71 I7 (io), D2 I/O75 J3 (io), D3 I/O79 J7 (io), D6 IO81 K6 (io), D9 I/O92 L3 (io), D12 I/O99 M3 (io), D15 I/O110 N6 (io), D18 I/O112 O7 (io), D19 I/O117 O2 (io), D20 I/O120 P7 (io), E1 I/O68 I4 (io), E2 I/O72 J0 (io), E3 I/O77 J5 (io), E18 I/O114 O5 (io), E19 I/O119 O0 (io), E20 I/O123 P4 (io), F2 I/O69 I5 (io), F3 I/O73 J1 (io), F4 I/O76 J4 (io), F17 I/O115 O4 (io), F18 I/O118 O1 (io), F19 I/O122 P5 (io), G2 I/O65 I1 (io), G3 I/O70 I6 (io), G18 I/O121 P6 (io), G19 I/O125 P2 (io), H2 I/O64 I0 (io), H3 I/O66 I2 (io), H4 I/O67 I3 (io), H17 I/O124 P3 (io), H18 I/O126 P1 (io), H19 I/O127 P0 (io), M1 I/O62 H1 (io), M2 I/O63 H0 (io), N2 I/O59 H4 (io), N3 I/O61 H2 (io), N4 I/O60 H3 (io), N17 I/O3 A3 (io), N18 I/O2 A2 (io), N19 I/O0 A0 (io), P2 I/O58 H5 (io), P3 I/O57 H6 (io), P18 I/O6 A6 (io), P19 I/O1 A1 (io), R2 I/O56 H7 (io), R3 I/O54 G1 (io), R4 I/O51 G4 (io), R18 I/O9 B1 (io), R19 I/O5 A5 (io), T2 I/O55 G0 (io), T3 I/O50 G5 (io), T18 I/O12 B4 (io), T19 I/O8 B0 (io), T20 I/O4 A4 (io), U2 I/O53 G2 (io), U3 I/O48 G7 (io), U9 I/O35 E3 (io), U12 I/O29 D2 (io), U13 I/O24 D7 (io), U15 I/O18 C5 (io), U18 I/O15 B7 (io), U19 I/O11 B3 (io), U20 I/O7 A7 (io), V2 I/O52 G3 (io), V4 I/O47 F7 (io), V5 I/O46 F6 (io), V6 I/O43 F3 (io), V7 I/O41 F1 (io), V8 I/O37 E5 (io), V9 I/O33 E1 (io), V12 I/O31 D0 (io), V13 I/O27 D4 (io), V14 I/O23 C0 (io), V15 I/O21 C2 (io), V16 I/O17 C6 (io), V17 I/O16 C7 (io), V19 I/O13 B5 (io), V20 I/O10 B2 (io), W2 I/O49 G6 (io), W4 I/O45 F5 (io), W5 I/O42 F2 (io), W6 I/O39 E7 (io), W7 I/O38 E6 (io), W8 I/O34 E2 (io), W13 I/O28 D3 (io), W14 I/O25 D6 (io), W15 I/O22 C1 (io), W16 I/O19 C4 (io), W19 I/O14 B6 (io), Y4 I/O44 F4 (io), Y5 I/O40 F0 (io), Y7 I/O36 E4 (io), Y8 I/O32 E0 (io), Y13 I/O30 D1 (io), Y14 I/O26 D5 (io), Y16 I/O20 C3 (io)
part B pins: A1 GND (power), A2 GND (power), A3 GND (power), A6 GND (power), A9 GND (power), A10 GND (power), A11 GND (power), A12 GND (power), A15 GND (power), A18 GND (power), A20 GND (power), B1 GND (power), B11 I11 (in), B20 GND (power), C3 VCC (power), C4 ~{ENABLE} (in), C10 I10 (in), C17 ~{TRST} (in), C18 VCC (power), D4 VCC (power), D5 VCC (power), D7 VCC (power), D10 I9 (in), D14 VCC (power), D16 VCC (power), D17 VCC (power), E4 TDO (out), E17 TDI (in), F1 GND (power), F20 GND (power), G1 I8 (in), G4 VCC (power), G17 VCC (power), G20 I12 (in), H1 GND (power), H20 GND (power), J4 I7 (in), J17 I13 (in), K2 CLK2 (in), K19 CLK3 (in), K20 GND (power), L1 GND (power), L2 CLK1 (in), L19 CLK0 (in), M4 I6 (in), M17 I0 (in), N1 GND (power), N20 GND (power), P1 I5 (io), P4 VCC (power), P17 VCC (power), P20 I1 (in), R1 GND (power), R20 GND (power), T4 TMS (in), T17 TCK (in), U4 VCC (power), U5 VCC (power), U7 VCC (power), U11 I2 (in), U14 VCC (power), U16 VCC (power), U17 VCC (power), V3 VCC (power), V11 I3 (in), V18 VCC (power), W1 GND (power), W10 I4 (in), W20 GND (power), Y1 GND (power), Y3 GND (power), Y6 GND (power), Y9 GND (power), Y10 GND (power), Y11 GND (power), Y12 GND (power), Y15 GND (power), Y18 GND (power), Y19 GND (power), Y20 GND (power)
part C pins: A4 NC, A19 NC, B2 NC, B9 NC, B10 NC, B12 NC, B18 NC, C11 NC, C19 NC, D8 NC, D11 NC, D13 NC, J1 NC, J2 NC, J3 NC, J18 NC, J19 NC, J20 NC, K1 NC, K3 NC, K4 NC, K17 NC, K18 NC, L3 NC, L4 NC, L17 NC, L18 NC, L20 NC, M3 NC, M18 NC, M19 NC, M20 NC, R17 NC, T1 NC, U1 NC, U6 NC, U8 NC, U10 NC, V1 NC, V10 NC, W3 NC, W9 NC, W11 NC, W12 NC, W17 NC, W18 NC, Y2 NC, Y17 NC

## M4A5-256/128-12YI
designator U?
High-Performance EE CMOS In-System Programmable Logic
footprint PQFP208_N (Shrink QFP, 208-Leads, Body 28x28mm, Pitch 0.5mm, IPC Medium Density)
footprint PQFP208_L (Shrink QFP, 208-Leads, Body 28x28mm, Pitch 0.5mm, IPC High Density)
footprint PQFP208_M (Shrink QFP, 208-Leads, Body 28x28mm, Pitch 0.5mm, IPC Low Density)
3D model M4A5-PQFP208 (208-Pin Plastic Quad Flat Pack (PQFP208))
part A pins: 3 I/O16 C7 (io), 4 I/O17 C6 (io), 5 I/O18 C5 (io), 6 I/O19 C4 (io), 7 I/O20 C3 (io), 8 I/O21 C2 (io), 9 I/O22 C1 (io), 10 I/O23 C0 (io), 13 I/O24 D7 (io), 14 I/O25 D6 (io), 15 I/O26 D5 (io), 16 I/O27 D4 (io), 17 I/O28 D3 (io), 18 I/O29 D2 (io), 19 I/O30 D1 (io), 20 I/O31 D0 (io), 32 I/O32 E0 (io), 33 I/O33 E1 (io), 34 I/O34 E2 (io), 35 I/O35 E3 (io), 36 I/O36 E4 (io), 37 I/O37 E5 (io), 38 I/O38 E6 (io), 39 I/O39 E7 (io), 42 I/O40 F0 (io), 43 I/O41 F1 (io), 44 I/O42 F2 (io), 45 I/O43 F3 (io), 46 I/O44 F4 (io), 47 I/O45 F5 (io), 48 I/O46 F6 (io), 49 I/O47 F7 (io), 54 I/O48 G7 (io), 55 I/O49 G6 (io), 56 I/O50 G5 (io), 57 I/O51 G4 (io), 58 I/O52 G3 (io), 59 I/O53 G2 (io), 60 I/O54 G1 (io), 61 I/O55 G0 (io), 64 I/O56 H7 (io), 65 I/O57 H6 (io), 66 I/O58 H5 (io), 67 I/O59 H4 (io), 68 I/O60 H3 (io), 69 I/O61 H2 (io), 70 I/O62 H1 (io), 71 I/O63 H0 (io), 190 I/O0 A0 (io), 191 I/O1 A1 (io), 192 I/O2 A2 (io), 193 I/O3 A3 (io), 194 I/O4 A4 (io), 195 I/O5 A5 (io), 196 I/O6 A6 (io), 197 I/O7 A7 (io), 200 I/O8 B0 (io), 201 I/O9 B1 (io), 202 I/O10 B2 (io), 203 I/O11 B3 (io), 204 I/O12 B4 (io), 205 I/O13 B5 (io), 206 I/O14 B6 (io), 207 I/O15 B7 (io)
part B pins: 86 I/O64 I0 (io), 87 I/O65 I1 (io), 88 I/O66 I2 (io), 89 I/O67 I3 (io), 90 I/O68 I4 (io), 91 I/O69 I5 (io), 92 I/O70 I6 (io), 93 I/O71 I7 (io), 96 I/O72 J0 (io), 97 I/O73 J1 (io), 98 I/O74 J2 (io), 99 I/O75 J3 (io), 100 I/O76 J4 (io), 101 I/O77 J5 (io), 102 I/O78 J6 (io), 103 I/O79 J7 (io), 107 I/O80 K7 (io), 108 I/O81 K6 (io), 109 I/O82 K5 (io), 110 I/O83 K4 (io), 111 I/O84 K3 (io), 112 I/O85 K2 (io), 113 I/O86 K1 (io), 114 I/O87 K0 (io), 117 I/O88 L7 (io), 118 I/O89 L6 (io), 119 I/O90 L5 (io), 120 I/O91 L4 (io), 121 I/O92 L3 (io), 122 I/O93 L2 (io), 123 I/O94 L1 (io), 124 I/O95 L0 (io), 136 I/O96 M0 (io), 137 I/O97 M1 (io), 138 I/O98 M2 (io), 139 I/O99 M3 (io), 140 I/O100 M4 (io), 141 I/O101 M5 (io), 142 I/O102 M6 (io), 143 I/O103 M7 (io), 146 I/O104 N0 (io), 147 I/O105 N1 (io), 148 I/O106 N2 (io), 149 I/O107 N3 (io), 150 I/O108 N4 (io), 151 I/O109 N5 (io), 152 I/O110 N6 (io), 153 I/O111 N7 (io), 158 I/O112 O7 (io), 159 I/O113 O6 (io), 160 I/O114 O5 (io), 161 I/O115 O4 (io), 162 I/O116 O3 (io), 163 I/O117 O2 (io), 164 I/O118 O1 (io), 165 I/O119 O0 (io), 168 I/O120 P7 (io), 169 I/O121 P6 (io), 170 I/O122 P5 (io), 171 I/O123 P4 (io), 172 I/O124 P3 (io), 173 I/O125 P2 (io), 174 I/O126 P1 (io), 175 I/O127 P0 (io)
part C pins: 1 GND (power), 2 TDI (in), 11 VCC (power), 12 GND (power), 21 I2 (in), 22 I3 (in), 23 GND (power), 24 VCC (power), 25 VCC (power), 26 GND (power), 27 GND (power), 28 VCC (power), 29 VCC (power), 30 GND (power), 31 I4 (in), 40 GND (power), 41 VCC (power), 50 TMS (in), 51 TCK (in), 52 GND (power), 53 GND (power), 62 GND (power), 63 VCC (power), 72 I5 (in), 73 I6 (in), 74 CLK1 (in), 75 VCC (power), 76 GND (power), 77 GND (power), 78 VCC (power), 79 VCC (power), 80 GND (power), 81 GND (power), 82 VCC (power), 83 CLK2 (in), 84 I7 (in), 85 I8 (in), 94 VCC (power), 95 GND (power), 104 GND (power), 105 GND (power), 106 ~{ENABLE} (in), 115 VCC (power), 116 GND (power), 125 I9 (in), 126 I10 (in), 127 GND (power), 128 VCC (power), 129 VCC (power), 130 GND (power), 131 GND (power), 132 VCC (power), 133 VCC (power), 134 GND (power), 135 I11 (in), 144 GND (power), 145 VCC (power), 154 ~{TRST} (in), 155 TDO (out), 156 GND (power), 157 GND (power), 166 GND (power), 167 VCC (power), 176 I12 (in), 177 I13 (in), 178 CLK3 (in), 179 VCC (power), 180 GND (power), 181 GND (power), 182 VCC (power), 183 VCC (power), 184 GND (power), 185 GND (power), 186 VCC (power), 187 CLK0 (in), 188 I0 (in), 189 I1 (in), 198 VCC (power), 199 GND (power), 208 GND (power)

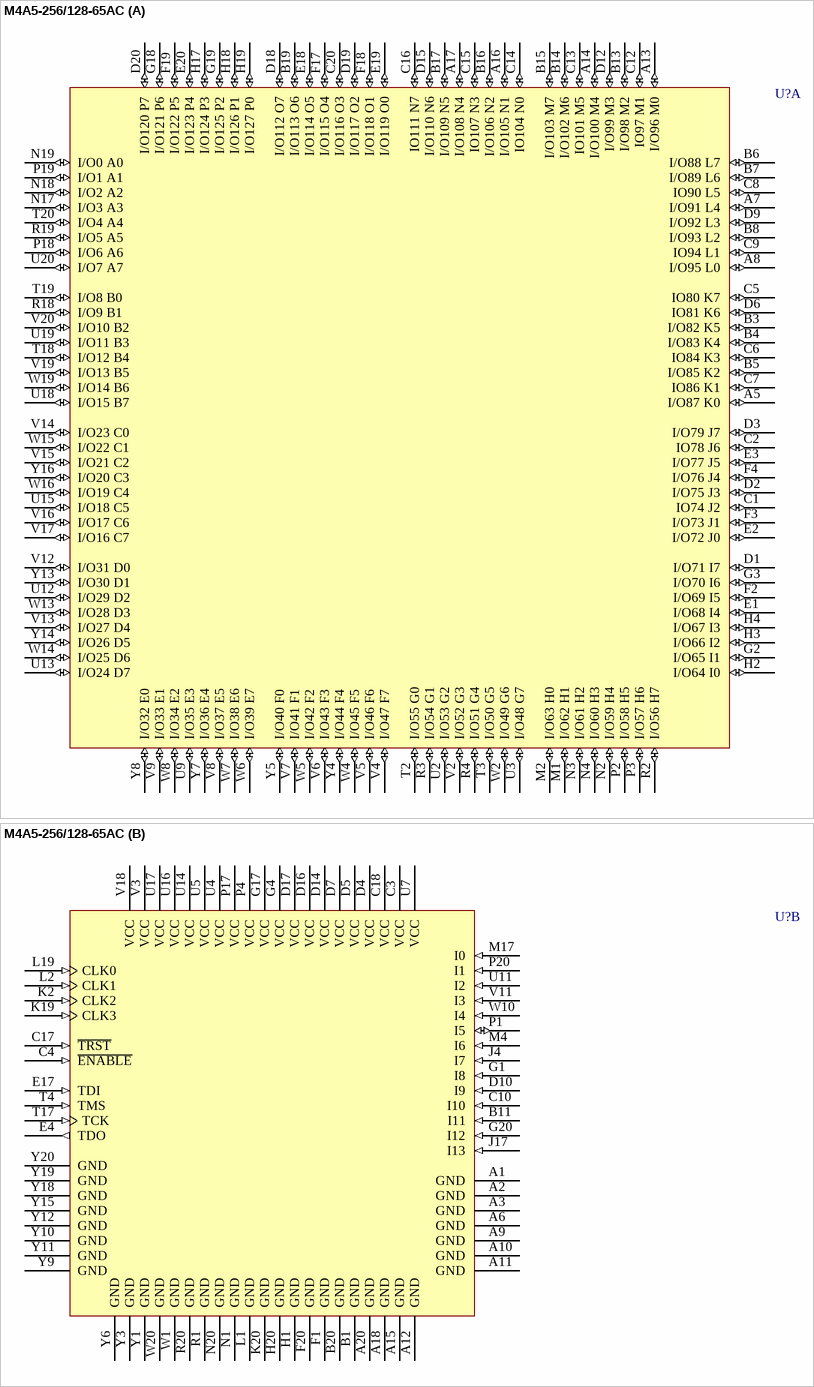
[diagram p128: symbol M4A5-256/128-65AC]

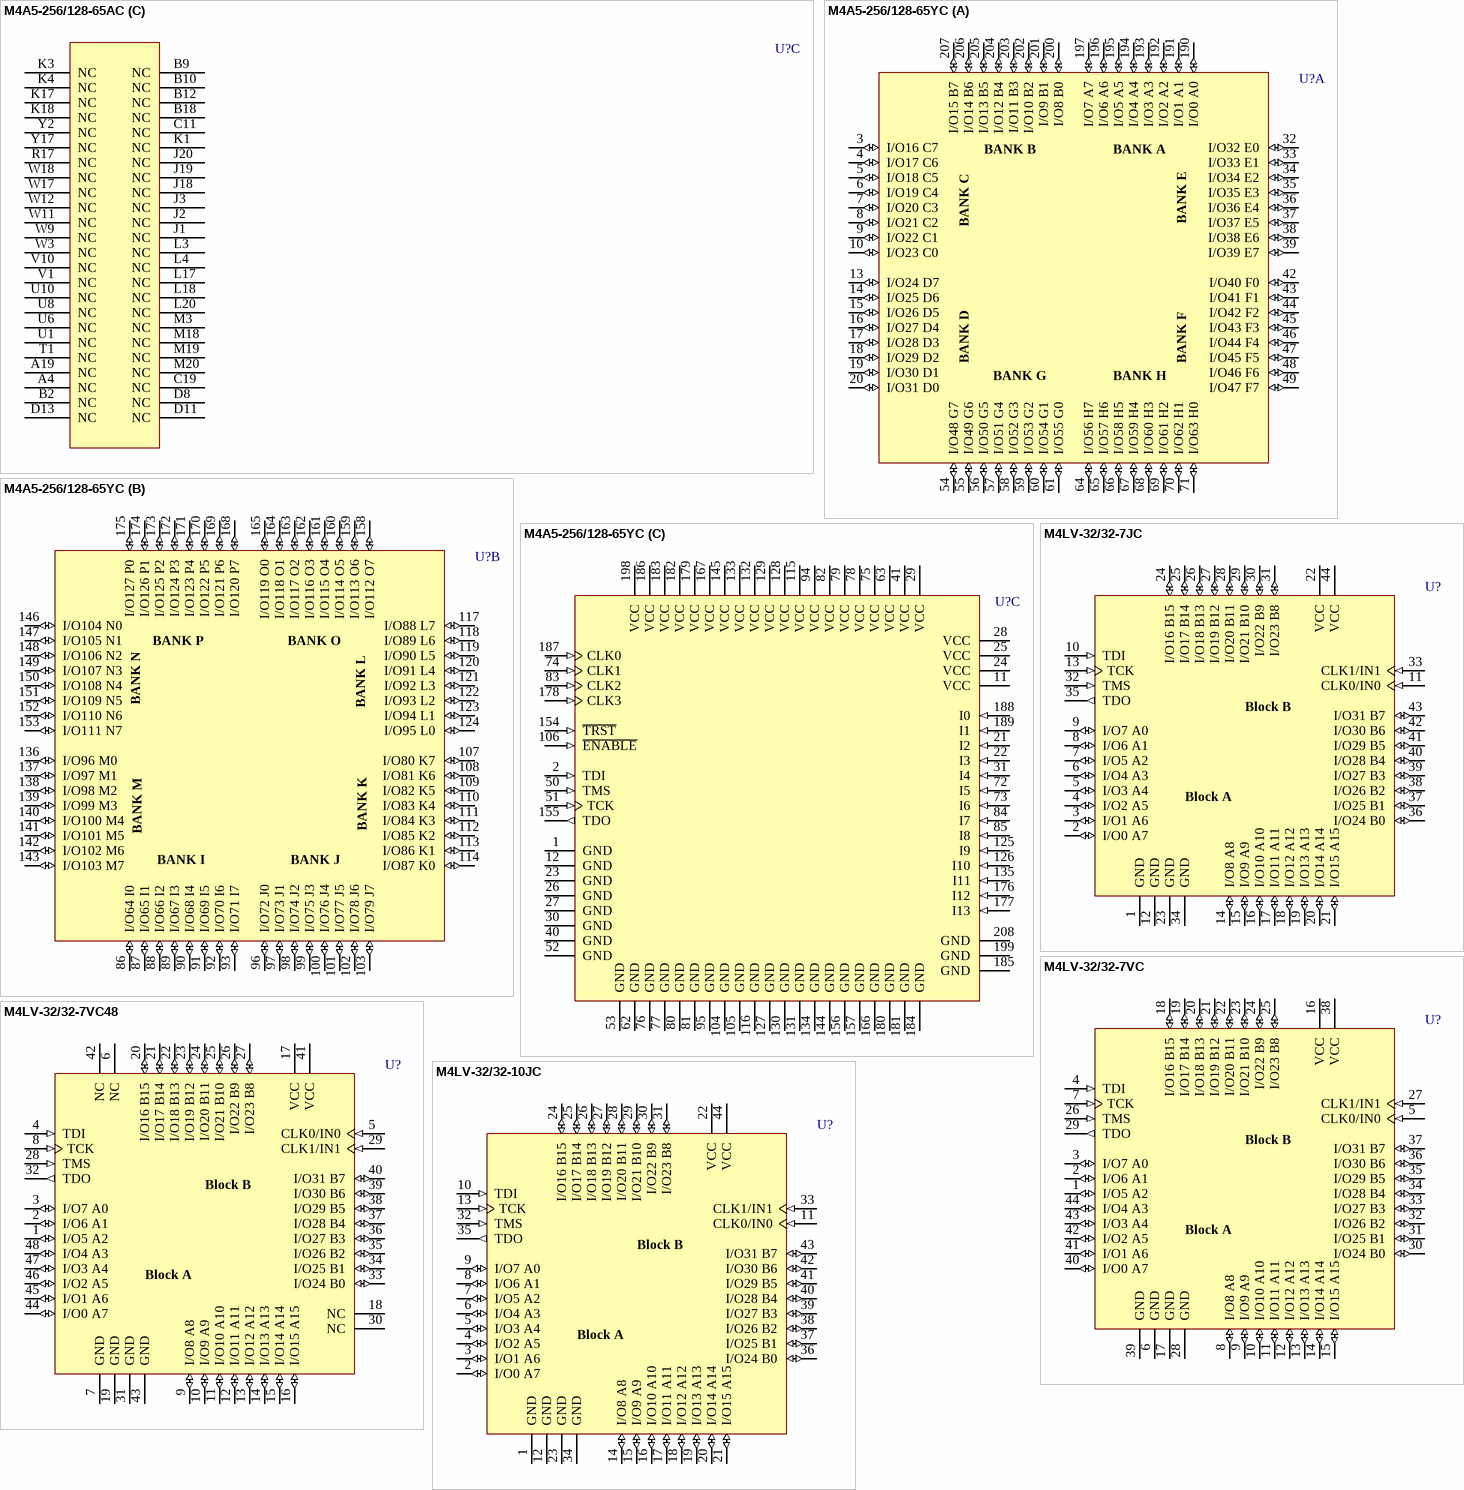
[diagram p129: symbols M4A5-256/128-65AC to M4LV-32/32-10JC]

## M4A5-256/128-65AC
designator U?
High-Performance EE CMOS In-System Programmable Logic
footprint SBGA256 (BGA, 256-Leads, Body 27x27mm, Pitch 1.27mm)
3D model M4A5-SBGA256 (256-Ball Super Ball Grid Array (SBGA256))
part A pins: A5 I/O87 K0 (io), A7 I/O91 L4 (io), A8 I/O95 L0 (io), A13 I/O96 M0 (io), A14 I/O100 M4 (io), A16 I/O105 N1 (io), A17 I/O108 N4 (io), B3 I/O82 K5 (io), B4 I/O83 K4 (io), B5 I/O85 K2 (io), B6 I/O88 L7 (io), B7 I/O89 L6 (io), B8 I/O93 L2 (io), B13 I/O98 M2 (io), B14 I/O102 M6 (io), B15 I/O103 M7 (io), B16 I/O106 N2 (io), B17 I/O109 N5 (io), B19 I/O113 O6 (io), C1 IO74 J2 (io), C2 IO78 J6 (io), C5 IO80 K7 (io), C6 IO84 K3 (io), C7 IO86 K1 (io), C8 IO90 L5 (io), C9 IO94 L1 (io), C12 IO97 M1 (io), C13 IO101 M5 (io), C14 IO104 N0 (io), C15 IO107 N3 (io), C16 IO111 N7 (io), C20 I/O116 O3 (io), D1 I/O71 I7 (io), D2 I/O75 J3 (io), D3 I/O79 J7 (io), D6 IO81 K6 (io), D9 I/O92 L3 (io), D12 I/O99 M3 (io), D15 I/O110 N6 (io), D18 I/O112 O7 (io), D19 I/O117 O2 (io), D20 I/O120 P7 (io), E1 I/O68 I4 (io), E2 I/O72 J0 (io), E3 I/O77 J5 (io), E18 I/O114 O5 (io), E19 I/O119 O0 (io), E20 I/O123 P4 (io), F2 I/O69 I5 (io), F3 I/O73 J1 (io), F4 I/O76 J4 (io), F17 I/O115 O4 (io), F18 I/O118 O1 (io), F19 I/O122 P5 (io), G2 I/O65 I1 (io), G3 I/O70 I6 (io), G18 I/O121 P6 (io), G19 I/O125 P2 (io), H2 I/O64 I0 (io), H3 I/O66 I2 (io), H4 I/O67 I3 (io), H17 I/O124 P3 (io), H18 I/O126 P1 (io), H19 I/O127 P0 (io), M1 I/O62 H1 (io), M2 I/O63 H0 (io), N2 I/O59 H4 (io), N3 I/O61 H2 (io), N4 I/O60 H3 (io), N17 I/O3 A3 (io), N18 I/O2 A2 (io), N19 I/O0 A0 (io), P2 I/O58 H5 (io), P3 I/O57 H6 (io), P18 I/O6 A6 (io), P19 I/O1 A1 (io), R2 I/O56 H7 (io), R3 I/O54 G1 (io), R4 I/O51 G4 (io), R18 I/O9 B1 (io), R19 I/O5 A5 (io), T2 I/O55 G0 (io), T3 I/O50 G5 (io), T18 I/O12 B4 (io), T19 I/O8 B0 (io), T20 I/O4 A4 (io), U2 I/O53 G2 (io), U3 I/O48 G7 (io), U9 I/O35 E3 (io), U12 I/O29 D2 (io), U13 I/O24 D7 (io), U15 I/O18 C5 (io), U18 I/O15 B7 (io), U19 I/O11 B3 (io), U20 I/O7 A7 (io), V2 I/O52 G3 (io), V4 I/O47 F7 (io), V5 I/O46 F6 (io), V6 I/O43 F3 (io), V7 I/O41 F1 (io), V8 I/O37 E5 (io), V9 I/O33 E1 (io), V12 I/O31 D0 (io), V13 I/O27 D4 (io), V14 I/O23 C0 (io), V15 I/O21 C2 (io), V16 I/O17 C6 (io), V17 I/O16 C7 (io), V19 I/O13 B5 (io), V20 I/O10 B2 (io), W2 I/O49 G6 (io), W4 I/O45 F5 (io), W5 I/O42 F2 (io), W6 I/O39 E7 (io), W7 I/O38 E6 (io), W8 I/O34 E2 (io), W13 I/O28 D3 (io), W14 I/O25 D6 (io), W15 I/O22 C1 (io), W16 I/O19 C4 (io), W19 I/O14 B6 (io), Y4 I/O44 F4 (io), Y5 I/O40 F0 (io), Y7 I/O36 E4 (io), Y8 I/O32 E0 (io), Y13 I/O30 D1 (io), Y14 I/O26 D5 (io), Y16 I/O20 C3 (io)
part B pins: A1 GND (power), A2 GND (power), A3 GND (power), A6 GND (power), A9 GND (power), A10 GND (power), A11 GND (power), A12 GND (power), A15 GND (power), A18 GND (power), A20 GND (power), B1 GND (power), B11 I11 (in), B20 GND (power), C3 VCC (power), C4 ~{ENABLE} (in), C10 I10 (in), C17 ~{TRST} (in), C18 VCC (power), D4 VCC (power), D5 VCC (power), D7 VCC (power), D10 I9 (in), D14 VCC (power), D16 VCC (power), D17 VCC (power), E4 TDO (out), E17 TDI (in), F1 GND (power), F20 GND (power), G1 I8 (in), G4 VCC (power), G17 VCC (power), G20 I12 (in), H1 GND (power), H20 GND (power), J4 I7 (in), J17 I13 (in), K2 CLK2 (in), K19 CLK3 (in), K20 GND (power), L1 GND (power), L2 CLK1 (in), L19 CLK0 (in), M4 I6 (in), M17 I0 (in), N1 GND (power), N20 GND (power), P1 I5 (io), P4 VCC (power), P17 VCC (power), P20 I1 (in), R1 GND (power), R20 GND (power), T4 TMS (in), T17 TCK (in), U4 VCC (power), U5 VCC (power), U7 VCC (power), U11 I2 (in), U14 VCC (power), U16 VCC (power), U17 VCC (power), V3 VCC (power), V11 I3 (in), V18 VCC (power), W1 GND (power), W10 I4 (in), W20 GND (power), Y1 GND (power), Y3 GND (power), Y6 GND (power), Y9 GND (power), Y10 GND (power), Y11 GND (power), Y12 GND (power), Y15 GND (power), Y18 GND (power), Y19 GND (power), Y20 GND (power)
part C pins: A4 NC, A19 NC, B2 NC, B9 NC, B10 NC, B12 NC, B18 NC, C11 NC, C19 NC, D8 NC, D11 NC, D13 NC, J1 NC, J2 NC, J3 NC, J18 NC, J19 NC, J20 NC, K1 NC, K3 NC, K4 NC, K17 NC, K18 NC, L3 NC, L4 NC, L17 NC, L18 NC, L20 NC, M3 NC, M18 NC, M19 NC, M20 NC, R17 NC, T1 NC, U1 NC, U6 NC, U8 NC, U10 NC, V1 NC, V10 NC, W3 NC, W9 NC, W11 NC, W12 NC, W17 NC, W18 NC, Y2 NC, Y17 NC

## M4A5-256/128-65YC
designator U?
High-Performance EE CMOS In-System Programmable Logic
footprint PQFP208_N (Shrink QFP, 208-Leads, Body 28x28mm, Pitch 0.5mm, IPC Medium Density)
footprint PQFP208_L (Shrink QFP, 208-Leads, Body 28x28mm, Pitch 0.5mm, IPC High Density)
footprint PQFP208_M (Shrink QFP, 208-Leads, Body 28x28mm, Pitch 0.5mm, IPC Low Density)
3D model M4A5-PQFP208 (208-Pin Plastic Quad Flat Pack (PQFP208))
part A pins: 3 I/O16 C7 (io), 4 I/O17 C6 (io), 5 I/O18 C5 (io), 6 I/O19 C4 (io), 7 I/O20 C3 (io), 8 I/O21 C2 (io), 9 I/O22 C1 (io), 10 I/O23 C0 (io), 13 I/O24 D7 (io), 14 I/O25 D6 (io), 15 I/O26 D5 (io), 16 I/O27 D4 (io), 17 I/O28 D3 (io), 18 I/O29 D2 (io), 19 I/O30 D1 (io), 20 I/O31 D0 (io), 32 I/O32 E0 (io), 33 I/O33 E1 (io), 34 I/O34 E2 (io), 35 I/O35 E3 (io), 36 I/O36 E4 (io), 37 I/O37 E5 (io), 38 I/O38 E6 (io), 39 I/O39 E7 (io), 42 I/O40 F0 (io), 43 I/O41 F1 (io), 44 I/O42 F2 (io), 45 I/O43 F3 (io), 46 I/O44 F4 (io), 47 I/O45 F5 (io), 48 I/O46 F6 (io), 49 I/O47 F7 (io), 54 I/O48 G7 (io), 55 I/O49 G6 (io), 56 I/O50 G5 (io), 57 I/O51 G4 (io), 58 I/O52 G3 (io), 59 I/O53 G2 (io), 60 I/O54 G1 (io), 61 I/O55 G0 (io), 64 I/O56 H7 (io), 65 I/O57 H6 (io), 66 I/O58 H5 (io), 67 I/O59 H4 (io), 68 I/O60 H3 (io), 69 I/O61 H2 (io), 70 I/O62 H1 (io), 71 I/O63 H0 (io), 190 I/O0 A0 (io), 191 I/O1 A1 (io), 192 I/O2 A2 (io), 193 I/O3 A3 (io), 194 I/O4 A4 (io), 195 I/O5 A5 (io), 196 I/O6 A6 (io), 197 I/O7 A7 (io), 200 I/O8 B0 (io), 201 I/O9 B1 (io), 202 I/O10 B2 (io), 203 I/O11 B3 (io), 204 I/O12 B4 (io), 205 I/O13 B5 (io), 206 I/O14 B6 (io), 207 I/O15 B7 (io)
part B pins: 86 I/O64 I0 (io), 87 I/O65 I1 (io), 88 I/O66 I2 (io), 89 I/O67 I3 (io), 90 I/O68 I4 (io), 91 I/O69 I5 (io), 92 I/O70 I6 (io), 93 I/O71 I7 (io), 96 I/O72 J0 (io), 97 I/O73 J1 (io), 98 I/O74 J2 (io), 99 I/O75 J3 (io), 100 I/O76 J4 (io), 101 I/O77 J5 (io), 102 I/O78 J6 (io), 103 I/O79 J7 (io), 107 I/O80 K7 (io), 108 I/O81 K6 (io), 109 I/O82 K5 (io), 110 I/O83 K4 (io), 111 I/O84 K3 (io), 112 I/O85 K2 (io), 113 I/O86 K1 (io), 114 I/O87 K0 (io), 117 I/O88 L7 (io), 118 I/O89 L6 (io), 119 I/O90 L5 (io), 120 I/O91 L4 (io), 121 I/O92 L3 (io), 122 I/O93 L2 (io), 123 I/O94 L1 (io), 124 I/O95 L0 (io), 136 I/O96 M0 (io), 137 I/O97 M1 (io), 138 I/O98 M2 (io), 139 I/O99 M3 (io), 140 I/O100 M4 (io), 141 I/O101 M5 (io), 142 I/O102 M6 (io), 143 I/O103 M7 (io), 146 I/O104 N0 (io), 147 I/O105 N1 (io), 148 I/O106 N2 (io), 149 I/O107 N3 (io), 150 I/O108 N4 (io), 151 I/O109 N5 (io), 152 I/O110 N6 (io), 153 I/O111 N7 (io), 158 I/O112 O7 (io), 159 I/O113 O6 (io), 160 I/O114 O5 (io), 161 I/O115 O4 (io), 162 I/O116 O3 (io), 163 I/O117 O2 (io), 164 I/O118 O1 (io), 165 I/O119 O0 (io), 168 I/O120 P7 (io), 169 I/O121 P6 (io), 170 I/O122 P5 (io), 171 I/O123 P4 (io), 172 I/O124 P3 (io), 173 I/O125 P2 (io), 174 I/O126 P1 (io), 175 I/O127 P0 (io)
part C pins: 1 GND (power), 2 TDI (in), 11 VCC (power), 12 GND (power), 21 I2 (in), 22 I3 (in), 23 GND (power), 24 VCC (power), 25 VCC (power), 26 GND (power), 27 GND (power), 28 VCC (power), 29 VCC (power), 30 GND (power), 31 I4 (in), 40 GND (power), 41 VCC (power), 50 TMS (in), 51 TCK (in), 52 GND (power), 53 GND (power), 62 GND (power), 63 VCC (power), 72 I5 (in), 73 I6 (in), 74 CLK1 (in), 75 VCC (power), 76 GND (power), 77 GND (power), 78 VCC (power), 79 VCC (power), 80 GND (power), 81 GND (power), 82 VCC (power), 83 CLK2 (in), 84 I7 (in), 85 I8 (in), 94 VCC (power), 95 GND (power), 104 GND (power), 105 GND (power), 106 ~{ENABLE} (in), 115 VCC (power), 116 GND (power), 125 I9 (in), 126 I10 (in), 127 GND (power), 128 VCC (power), 129 VCC (power), 130 GND (power), 131 GND (power), 132 VCC (power), 133 VCC (power), 134 GND (power), 135 I11 (in), 144 GND (power), 145 VCC (power), 154 ~{TRST} (in), 155 TDO (out), 156 GND (power), 157 GND (power), 166 GND (power), 167 VCC (power), 176 I12 (in), 177 I13 (in), 178 CLK3 (in), 179 VCC (power), 180 GND (power), 181 GND (power), 182 VCC (power), 183 VCC (power), 184 GND (power), 185 GND (power), 186 VCC (power), 187 CLK0 (in), 188 I0 (in), 189 I1 (in), 198 VCC (power), 199 GND (power), 208 GND (power)

## M4LV-32/32-7JC
designator U?
High-Performance EE CMOS In-System Programmable Logic
footprint PLCC44_N (Leaded Chip Carrier, 44-Leads, Body 16.6x16.6mm, Pitch 1.27mm, IPC Medium Density)
footprint PLCC44_L (Leaded Chip Carrier, 44-Leads, Body 16.6x16.6mm, Pitch 1.27mm, IPC High Density)
footprint PLCC44_M (Leaded Chip Carrier, 44-Leads, Body 16.6x16.6mm, Pitch 1.27mm, IPC Low Density)
3D model M4LV-PLCC44 (44-Pin Leaded Chip Carrier 1.27 mm Pitch)
pins: 1 GND (power), 2 I/O0 A7 (io), 3 I/O1 A6 (io), 4 I/O2 A5 (io), 5 I/O3 A4 (io), 6 I/O4 A3 (io), 7 I/O5 A2 (io), 8 I/O6 A1 (io), 9 I/O7 A0 (io), 10 TDI (in), 11 CLK0/IN0 (in), 12 GND (power), 13 TCK (in), 14 I/O8 A8 (io), 15 I/O9 A9 (io), 16 I/O10 A10 (io), 17 I/O11 A11 (io), 18 I/O12 A12 (io), 19 I/O13 A13 (io), 20 I/O14 A14 (io), 21 I/O15 A15 (io), 22 VCC (power), 23 GND (power), 24 I/O16 B15 (io), 25 I/O17 B14 (io), 26 I/O18 B13 (io), 27 I/O19 B12 (io), 28 I/O20 B11 (io), 29 I/O21 B10 (io), 30 I/O22 B9 (io), 31 I/O23 B8 (io), 32 TMS (in), 33 CLK1/IN1 (in), 34 GND (power), 35 TDO (out), 36 I/O24 B0 (io), 37 I/O25 B1 (io), 38 I/O26 B2 (io), 39 I/O27 B3 (io), 40 I/O28 B4 (io), 41 I/O29 B5 (io), 42 I/O30 B6 (io), 43 I/O31 B7 (io), 44 VCC (power)

## M4LV-32/32-7VC
designator U?
High-Performance EE CMOS In-System Programmable Logic
footprint TQFP44_N (Thin QFP, 44-Leads, Body 10x10mm, Pitch 0.8mm, IPC Medium Density)
footprint TQFP44_L (Thin QFP, 44-Leads, Body 10x10mm, Pitch 0.8mm, IPC High Density)
footprint TQFP44_M (Thin QFP, 44-Leads, Body 10x10mm, Pitch 0.8mm, IPC Low Density)
3D model M4LV-TQFP44 (44-Pin Thin Quad Flat Pack 0.8 mm Pitch)
pins: 1 I/O5 A2 (io), 2 I/O6 A1 (io), 3 I/O7 A0 (io), 4 TDI (in), 5 CLK0/IN0 (in), 6 GND (power), 7 TCK (in), 8 I/O8 A8 (io), 9 I/O9 A9 (io), 10 I/O10 A10 (io), 11 I/O11 A11 (io), 12 I/O12 A12 (io), 13 I/O13 A13 (io), 14 I/O14 A14 (io), 15 I/O15 A15 (io), 16 VCC (power), 17 GND (power), 18 I/O16 B15 (io), 19 I/O17 B14 (io), 20 I/O18 B13 (io), 21 I/O19 B12 (io), 22 I/O20 B11 (io), 23 I/O21 B10 (io), 24 I/O22 B9 (io), 25 I/O23 B8 (io), 26 TMS (in), 27 CLK1/IN1 (in), 28 GND (power), 29 TDO (out), 30 I/O24 B0 (io), 31 I/O25 B1 (io), 32 I/O26 B2 (io), 33 I/O27 B3 (io), 34 I/O28 B4 (io), 35 I/O29 B5 (io), 36 I/O30 B6 (io), 37 I/O31 B7 (io), 38 VCC (power), 39 GND (power), 40 I/O0 A7 (io), 41 I/O1 A6 (io), 42 I/O2 A5 (io), 43 I/O3 A4 (io), 44 I/O4 A3 (io)

## M4LV-32/32-7VC48
designator U?
High-Performance EE CMOS In-System Programmable Logic
footprint TQFP48_N (Thin QFP, 48-Leads, Body 7x7mm, Pitch 0.5mm, IPC Medium Density)
footprint TQFP48_L (Thin QFP, 48-Leads, Body 7x7mm, Pitch 0.5mm, IPC High Density)
footprint TQFP48_M (Thin QFP, 48-Leads, Body 7x7mm, Pitch 0.5mm, IPC Low Density)
3D model M4LV-TQFP48 (48-Pin Thin Quad Flat Pack 0.5 mm Pitch)
pins: 1 I/O5 A2 (io), 2 I/O6 A1 (io), 3 I/O7 A0 (io), 4 TDI (in), 5 CLK0/IN0 (in), 6 NC, 7 GND (power), 8 TCK (in), 9 I/O8 A8 (io), 10 I/O9 A9 (io), 11 I/O10 A10 (io), 12 I/O11 A11 (io), 13 I/O12 A12 (io), 14 I/O13 A13 (io), 15 I/O14 A14 (io), 16 I/O15 A15 (io), 17 VCC (power), 18 NC, 19 GND (power), 20 I/O16 B15 (io), 21 I/O17 B14 (io), 22 I/O18 B13 (io), 23 I/O19 B12 (io), 24 I/O20 B11 (io), 25 I/O21 B10 (io), 26 I/O22 B9 (io), 27 I/O23 B8 (io), 28 TMS (in), 29 CLK1/IN1 (in), 30 NC, 31 GND (power), 32 TDO (out), 33 I/O24 B0 (io), 34 I/O25 B1 (io), 35 I/O26 B2 (io), 36 I/O27 B3 (io), 37 I/O28 B4 (io), 38 I/O29 B5 (io), 39 I/O30 B6 (io), 40 I/O31 B7 (io), 41 VCC (power), 42 NC, 43 GND (power), 44 I/O0 A7 (io), 45 I/O1 A6 (io), 46 I/O2 A5 (io), 47 I/O3 A4 (io), 48 I/O4 A3 (io)

## M4LV-32/32-10JC
designator U?
High-Performance EE CMOS In-System Programmable Logic
footprint PLCC44_N (Leaded Chip Carrier, 44-Leads, Body 16.6x16.6mm, Pitch 1.27mm, IPC Medium Density)
footprint PLCC44_L (Leaded Chip Carrier, 44-Leads, Body 16.6x16.6mm, Pitch 1.27mm, IPC High Density)
footprint PLCC44_M (Leaded Chip Carrier, 44-Leads, Body 16.6x16.6mm, Pitch 1.27mm, IPC Low Density)
3D model M4LV-PLCC44 (44-Pin Leaded Chip Carrier 1.27 mm Pitch)
pins: 1 GND (power), 2 I/O0 A7 (io), 3 I/O1 A6 (io), 4 I/O2 A5 (io), 5 I/O3 A4 (io), 6 I/O4 A3 (io), 7 I/O5 A2 (io), 8 I/O6 A1 (io), 9 I/O7 A0 (io), 10 TDI (in), 11 CLK0/IN0 (in), 12 GND (power), 13 TCK (in), 14 I/O8 A8 (io), 15 I/O9 A9 (io), 16 I/O10 A10 (io), 17 I/O11 A11 (io), 18 I/O12 A12 (io), 19 I/O13 A13 (io), 20 I/O14 A14 (io), 21 I/O15 A15 (io), 22 VCC (power), 23 GND (power), 24 I/O16 B15 (io), 25 I/O17 B14 (io), 26 I/O18 B13 (io), 27 I/O19 B12 (io), 28 I/O20 B11 (io), 29 I/O21 B10 (io), 30 I/O22 B9 (io), 31 I/O23 B8 (io), 32 TMS (in), 33 CLK1/IN1 (in), 34 GND (power), 35 TDO (out), 36 I/O24 B0 (io), 37 I/O25 B1 (io), 38 I/O26 B2 (io), 39 I/O27 B3 (io), 40 I/O28 B4 (io), 41 I/O29 B5 (io), 42 I/O30 B6 (io), 43 I/O31 B7 (io), 44 VCC (power)

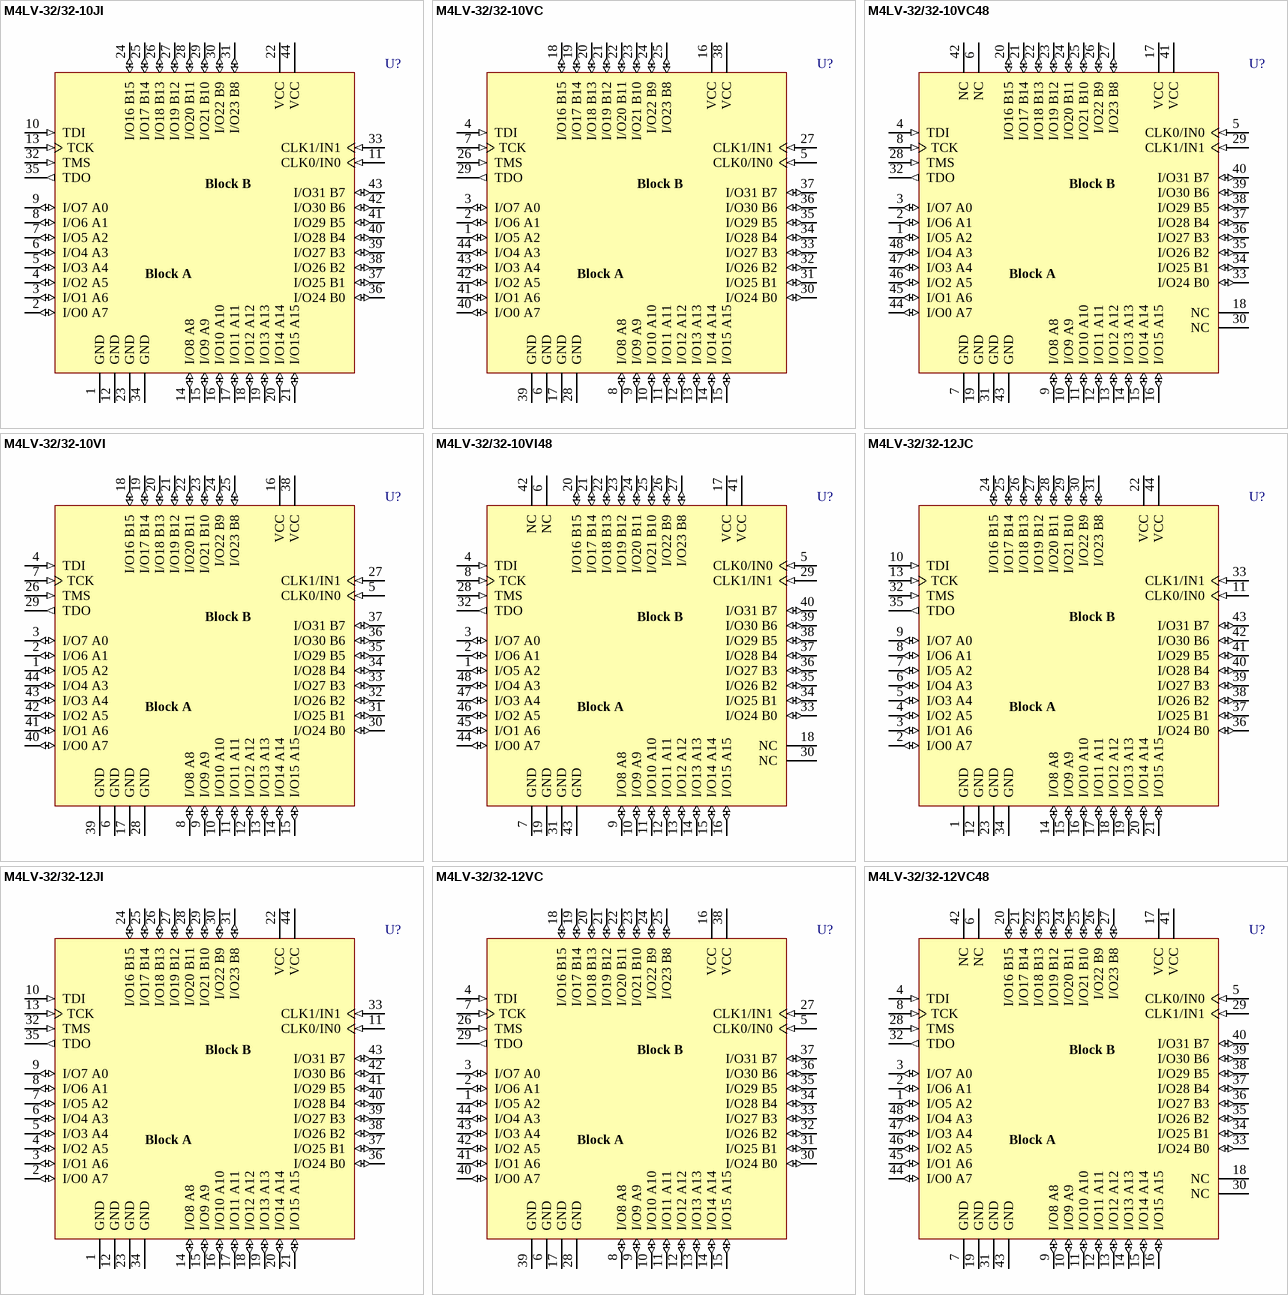
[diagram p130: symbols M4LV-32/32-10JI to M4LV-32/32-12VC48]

## M4LV-32/32-10JI
designator U?
High-Performance EE CMOS In-System Programmable Logic
footprint PLCC44_N (Leaded Chip Carrier, 44-Leads, Body 16.6x16.6mm, Pitch 1.27mm, IPC Medium Density)
footprint PLCC44_L (Leaded Chip Carrier, 44-Leads, Body 16.6x16.6mm, Pitch 1.27mm, IPC High Density)
footprint PLCC44_M (Leaded Chip Carrier, 44-Leads, Body 16.6x16.6mm, Pitch 1.27mm, IPC Low Density)
3D model M4LV-PLCC44 (44-Pin Leaded Chip Carrier 1.27 mm Pitch)
pins: 1 GND (power), 2 I/O0 A7 (io), 3 I/O1 A6 (io), 4 I/O2 A5 (io), 5 I/O3 A4 (io), 6 I/O4 A3 (io), 7 I/O5 A2 (io), 8 I/O6 A1 (io), 9 I/O7 A0 (io), 10 TDI (in), 11 CLK0/IN0 (in), 12 GND (power), 13 TCK (in), 14 I/O8 A8 (io), 15 I/O9 A9 (io), 16 I/O10 A10 (io), 17 I/O11 A11 (io), 18 I/O12 A12 (io), 19 I/O13 A13 (io), 20 I/O14 A14 (io), 21 I/O15 A15 (io), 22 VCC (power), 23 GND (power), 24 I/O16 B15 (io), 25 I/O17 B14 (io), 26 I/O18 B13 (io), 27 I/O19 B12 (io), 28 I/O20 B11 (io), 29 I/O21 B10 (io), 30 I/O22 B9 (io), 31 I/O23 B8 (io), 32 TMS (in), 33 CLK1/IN1 (in), 34 GND (power), 35 TDO (out), 36 I/O24 B0 (io), 37 I/O25 B1 (io), 38 I/O26 B2 (io), 39 I/O27 B3 (io), 40 I/O28 B4 (io), 41 I/O29 B5 (io), 42 I/O30 B6 (io), 43 I/O31 B7 (io), 44 VCC (power)

## M4LV-32/32-10VC
designator U?
High-Performance EE CMOS In-System Programmable Logic
footprint TQFP44_N (Thin QFP, 44-Leads, Body 10x10mm, Pitch 0.8mm, IPC Medium Density)
footprint TQFP44_L (Thin QFP, 44-Leads, Body 10x10mm, Pitch 0.8mm, IPC High Density)
footprint TQFP44_M (Thin QFP, 44-Leads, Body 10x10mm, Pitch 0.8mm, IPC Low Density)
3D model M4LV-TQFP44 (44-Pin Thin Quad Flat Pack 0.8 mm Pitch)
pins: 1 I/O5 A2 (io), 2 I/O6 A1 (io), 3 I/O7 A0 (io), 4 TDI (in), 5 CLK0/IN0 (in), 6 GND (power), 7 TCK (in), 8 I/O8 A8 (io), 9 I/O9 A9 (io), 10 I/O10 A10 (io), 11 I/O11 A11 (io), 12 I/O12 A12 (io), 13 I/O13 A13 (io), 14 I/O14 A14 (io), 15 I/O15 A15 (io), 16 VCC (power), 17 GND (power), 18 I/O16 B15 (io), 19 I/O17 B14 (io), 20 I/O18 B13 (io), 21 I/O19 B12 (io), 22 I/O20 B11 (io), 23 I/O21 B10 (io), 24 I/O22 B9 (io), 25 I/O23 B8 (io), 26 TMS (in), 27 CLK1/IN1 (in), 28 GND (power), 29 TDO (out), 30 I/O24 B0 (io), 31 I/O25 B1 (io), 32 I/O26 B2 (io), 33 I/O27 B3 (io), 34 I/O28 B4 (io), 35 I/O29 B5 (io), 36 I/O30 B6 (io), 37 I/O31 B7 (io), 38 VCC (power), 39 GND (power), 40 I/O0 A7 (io), 41 I/O1 A6 (io), 42 I/O2 A5 (io), 43 I/O3 A4 (io), 44 I/O4 A3 (io)

## M4LV-32/32-10VC48
designator U?
High-Performance EE CMOS In-System Programmable Logic
footprint TQFP48_N (Thin QFP, 48-Leads, Body 7x7mm, Pitch 0.5mm, IPC Medium Density)
footprint TQFP48_L (Thin QFP, 48-Leads, Body 7x7mm, Pitch 0.5mm, IPC High Density)
footprint TQFP48_M (Thin QFP, 48-Leads, Body 7x7mm, Pitch 0.5mm, IPC Low Density)
3D model M4LV-TQFP48 (48-Pin Thin Quad Flat Pack 0.5 mm Pitch)
pins: 1 I/O5 A2 (io), 2 I/O6 A1 (io), 3 I/O7 A0 (io), 4 TDI (in), 5 CLK0/IN0 (in), 6 NC, 7 GND (power), 8 TCK (in), 9 I/O8 A8 (io), 10 I/O9 A9 (io), 11 I/O10 A10 (io), 12 I/O11 A11 (io), 13 I/O12 A12 (io), 14 I/O13 A13 (io), 15 I/O14 A14 (io), 16 I/O15 A15 (io), 17 VCC (power), 18 NC, 19 GND (power), 20 I/O16 B15 (io), 21 I/O17 B14 (io), 22 I/O18 B13 (io), 23 I/O19 B12 (io), 24 I/O20 B11 (io), 25 I/O21 B10 (io), 26 I/O22 B9 (io), 27 I/O23 B8 (io), 28 TMS (in), 29 CLK1/IN1 (in), 30 NC, 31 GND (power), 32 TDO (out), 33 I/O24 B0 (io), 34 I/O25 B1 (io), 35 I/O26 B2 (io), 36 I/O27 B3 (io), 37 I/O28 B4 (io), 38 I/O29 B5 (io), 39 I/O30 B6 (io), 40 I/O31 B7 (io), 41 VCC (power), 42 NC, 43 GND (power), 44 I/O0 A7 (io), 45 I/O1 A6 (io), 46 I/O2 A5 (io), 47 I/O3 A4 (io), 48 I/O4 A3 (io)

## M4LV-32/32-10VI
designator U?
High-Performance EE CMOS In-System Programmable Logic
footprint TQFP44_N (Thin QFP, 44-Leads, Body 10x10mm, Pitch 0.8mm, IPC Medium Density)
footprint TQFP44_L (Thin QFP, 44-Leads, Body 10x10mm, Pitch 0.8mm, IPC High Density)
footprint TQFP44_M (Thin QFP, 44-Leads, Body 10x10mm, Pitch 0.8mm, IPC Low Density)
3D model M4LV-TQFP44 (44-Pin Thin Quad Flat Pack 0.8 mm Pitch)
pins: 1 I/O5 A2 (io), 2 I/O6 A1 (io), 3 I/O7 A0 (io), 4 TDI (in), 5 CLK0/IN0 (in), 6 GND (power), 7 TCK (in), 8 I/O8 A8 (io), 9 I/O9 A9 (io), 10 I/O10 A10 (io), 11 I/O11 A11 (io), 12 I/O12 A12 (io), 13 I/O13 A13 (io), 14 I/O14 A14 (io), 15 I/O15 A15 (io), 16 VCC (power), 17 GND (power), 18 I/O16 B15 (io), 19 I/O17 B14 (io), 20 I/O18 B13 (io), 21 I/O19 B12 (io), 22 I/O20 B11 (io), 23 I/O21 B10 (io), 24 I/O22 B9 (io), 25 I/O23 B8 (io), 26 TMS (in), 27 CLK1/IN1 (in), 28 GND (power), 29 TDO (out), 30 I/O24 B0 (io), 31 I/O25 B1 (io), 32 I/O26 B2 (io), 33 I/O27 B3 (io), 34 I/O28 B4 (io), 35 I/O29 B5 (io), 36 I/O30 B6 (io), 37 I/O31 B7 (io), 38 VCC (power), 39 GND (power), 40 I/O0 A7 (io), 41 I/O1 A6 (io), 42 I/O2 A5 (io), 43 I/O3 A4 (io), 44 I/O4 A3 (io)

## M4LV-32/32-10VI48
designator U?
High-Performance EE CMOS In-System Programmable Logic
footprint TQFP48_N (Thin QFP, 48-Leads, Body 7x7mm, Pitch 0.5mm, IPC Medium Density)
footprint TQFP48_L (Thin QFP, 48-Leads, Body 7x7mm, Pitch 0.5mm, IPC High Density)
footprint TQFP48_M (Thin QFP, 48-Leads, Body 7x7mm, Pitch 0.5mm, IPC Low Density)
3D model M4LV-TQFP48 (48-Pin Thin Quad Flat Pack 0.5 mm Pitch)
pins: 1 I/O5 A2 (io), 2 I/O6 A1 (io), 3 I/O7 A0 (io), 4 TDI (in), 5 CLK0/IN0 (in), 6 NC, 7 GND (power), 8 TCK (in), 9 I/O8 A8 (io), 10 I/O9 A9 (io), 11 I/O10 A10 (io), 12 I/O11 A11 (io), 13 I/O12 A12 (io), 14 I/O13 A13 (io), 15 I/O14 A14 (io), 16 I/O15 A15 (io), 17 VCC (power), 18 NC, 19 GND (power), 20 I/O16 B15 (io), 21 I/O17 B14 (io), 22 I/O18 B13 (io), 23 I/O19 B12 (io), 24 I/O20 B11 (io), 25 I/O21 B10 (io), 26 I/O22 B9 (io), 27 I/O23 B8 (io), 28 TMS (in), 29 CLK1/IN1 (in), 30 NC, 31 GND (power), 32 TDO (out), 33 I/O24 B0 (io), 34 I/O25 B1 (io), 35 I/O26 B2 (io), 36 I/O27 B3 (io), 37 I/O28 B4 (io), 38 I/O29 B5 (io), 39 I/O30 B6 (io), 40 I/O31 B7 (io), 41 VCC (power), 42 NC, 43 GND (power), 44 I/O0 A7 (io), 45 I/O1 A6 (io), 46 I/O2 A5 (io), 47 I/O3 A4 (io), 48 I/O4 A3 (io)

## M4LV-32/32-12JC
designator U?
High-Performance EE CMOS In-System Programmable Logic
footprint PLCC44_N (Leaded Chip Carrier, 44-Leads, Body 16.6x16.6mm, Pitch 1.27mm, IPC Medium Density)
footprint PLCC44_L (Leaded Chip Carrier, 44-Leads, Body 16.6x16.6mm, Pitch 1.27mm, IPC High Density)
footprint PLCC44_M (Leaded Chip Carrier, 44-Leads, Body 16.6x16.6mm, Pitch 1.27mm, IPC Low Density)
3D model M4LV-PLCC44 (44-Pin Leaded Chip Carrier 1.27 mm Pitch)
pins: 1 GND (power), 2 I/O0 A7 (io), 3 I/O1 A6 (io), 4 I/O2 A5 (io), 5 I/O3 A4 (io), 6 I/O4 A3 (io), 7 I/O5 A2 (io), 8 I/O6 A1 (io), 9 I/O7 A0 (io), 10 TDI (in), 11 CLK0/IN0 (in), 12 GND (power), 13 TCK (in), 14 I/O8 A8 (io), 15 I/O9 A9 (io), 16 I/O10 A10 (io), 17 I/O11 A11 (io), 18 I/O12 A12 (io), 19 I/O13 A13 (io), 20 I/O14 A14 (io), 21 I/O15 A15 (io), 22 VCC (power), 23 GND (power), 24 I/O16 B15 (io), 25 I/O17 B14 (io), 26 I/O18 B13 (io), 27 I/O19 B12 (io), 28 I/O20 B11 (io), 29 I/O21 B10 (io), 30 I/O22 B9 (io), 31 I/O23 B8 (io), 32 TMS (in), 33 CLK1/IN1 (in), 34 GND (power), 35 TDO (out), 36 I/O24 B0 (io), 37 I/O25 B1 (io), 38 I/O26 B2 (io), 39 I/O27 B3 (io), 40 I/O28 B4 (io), 41 I/O29 B5 (io), 42 I/O30 B6 (io), 43 I/O31 B7 (io), 44 VCC (power)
